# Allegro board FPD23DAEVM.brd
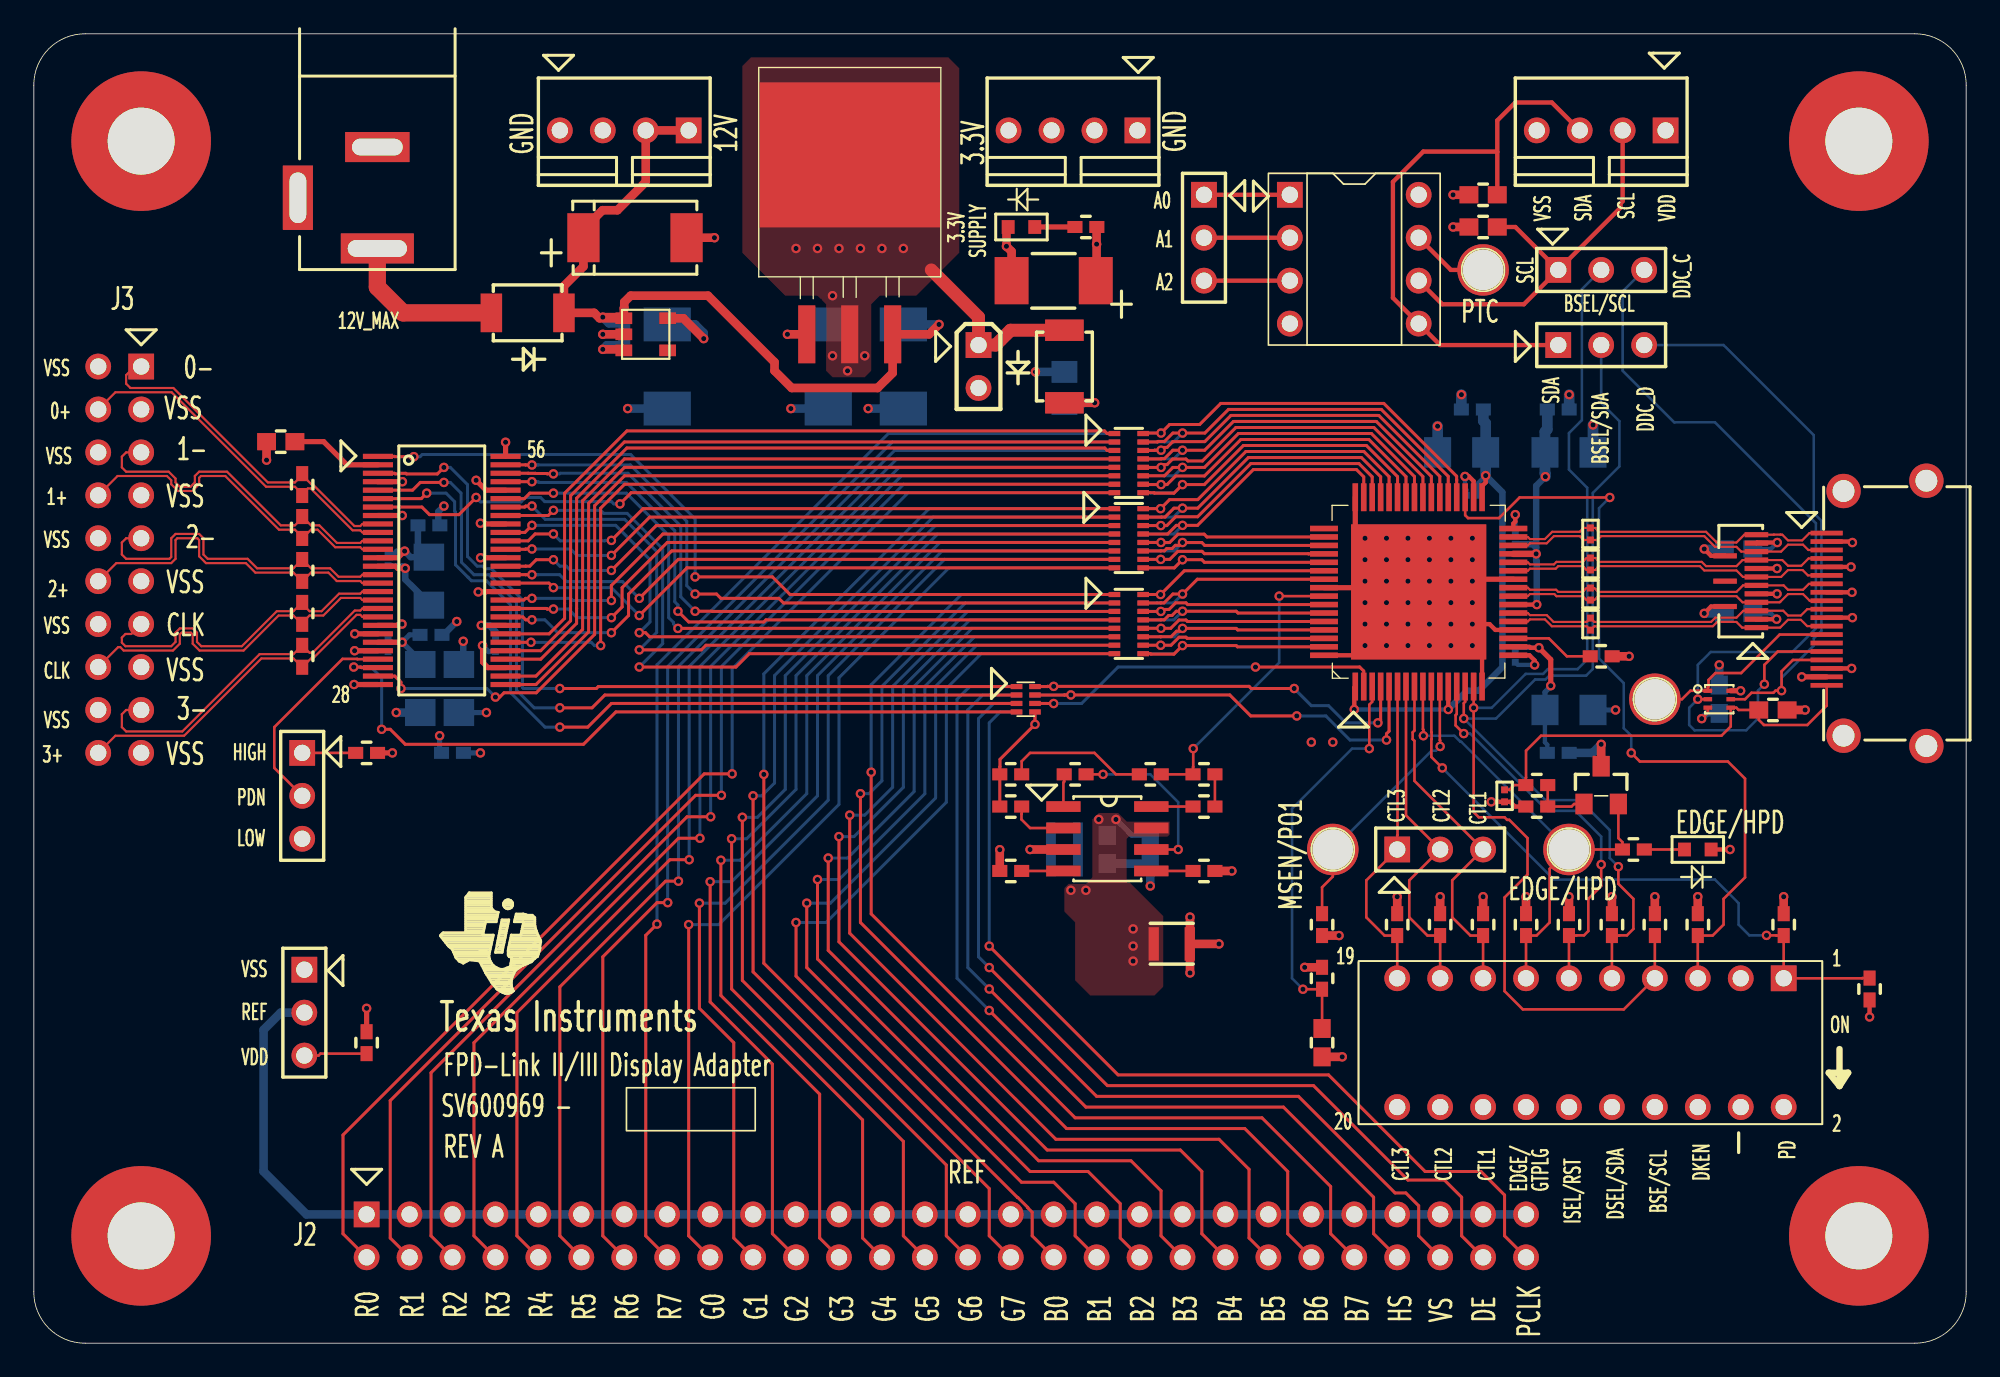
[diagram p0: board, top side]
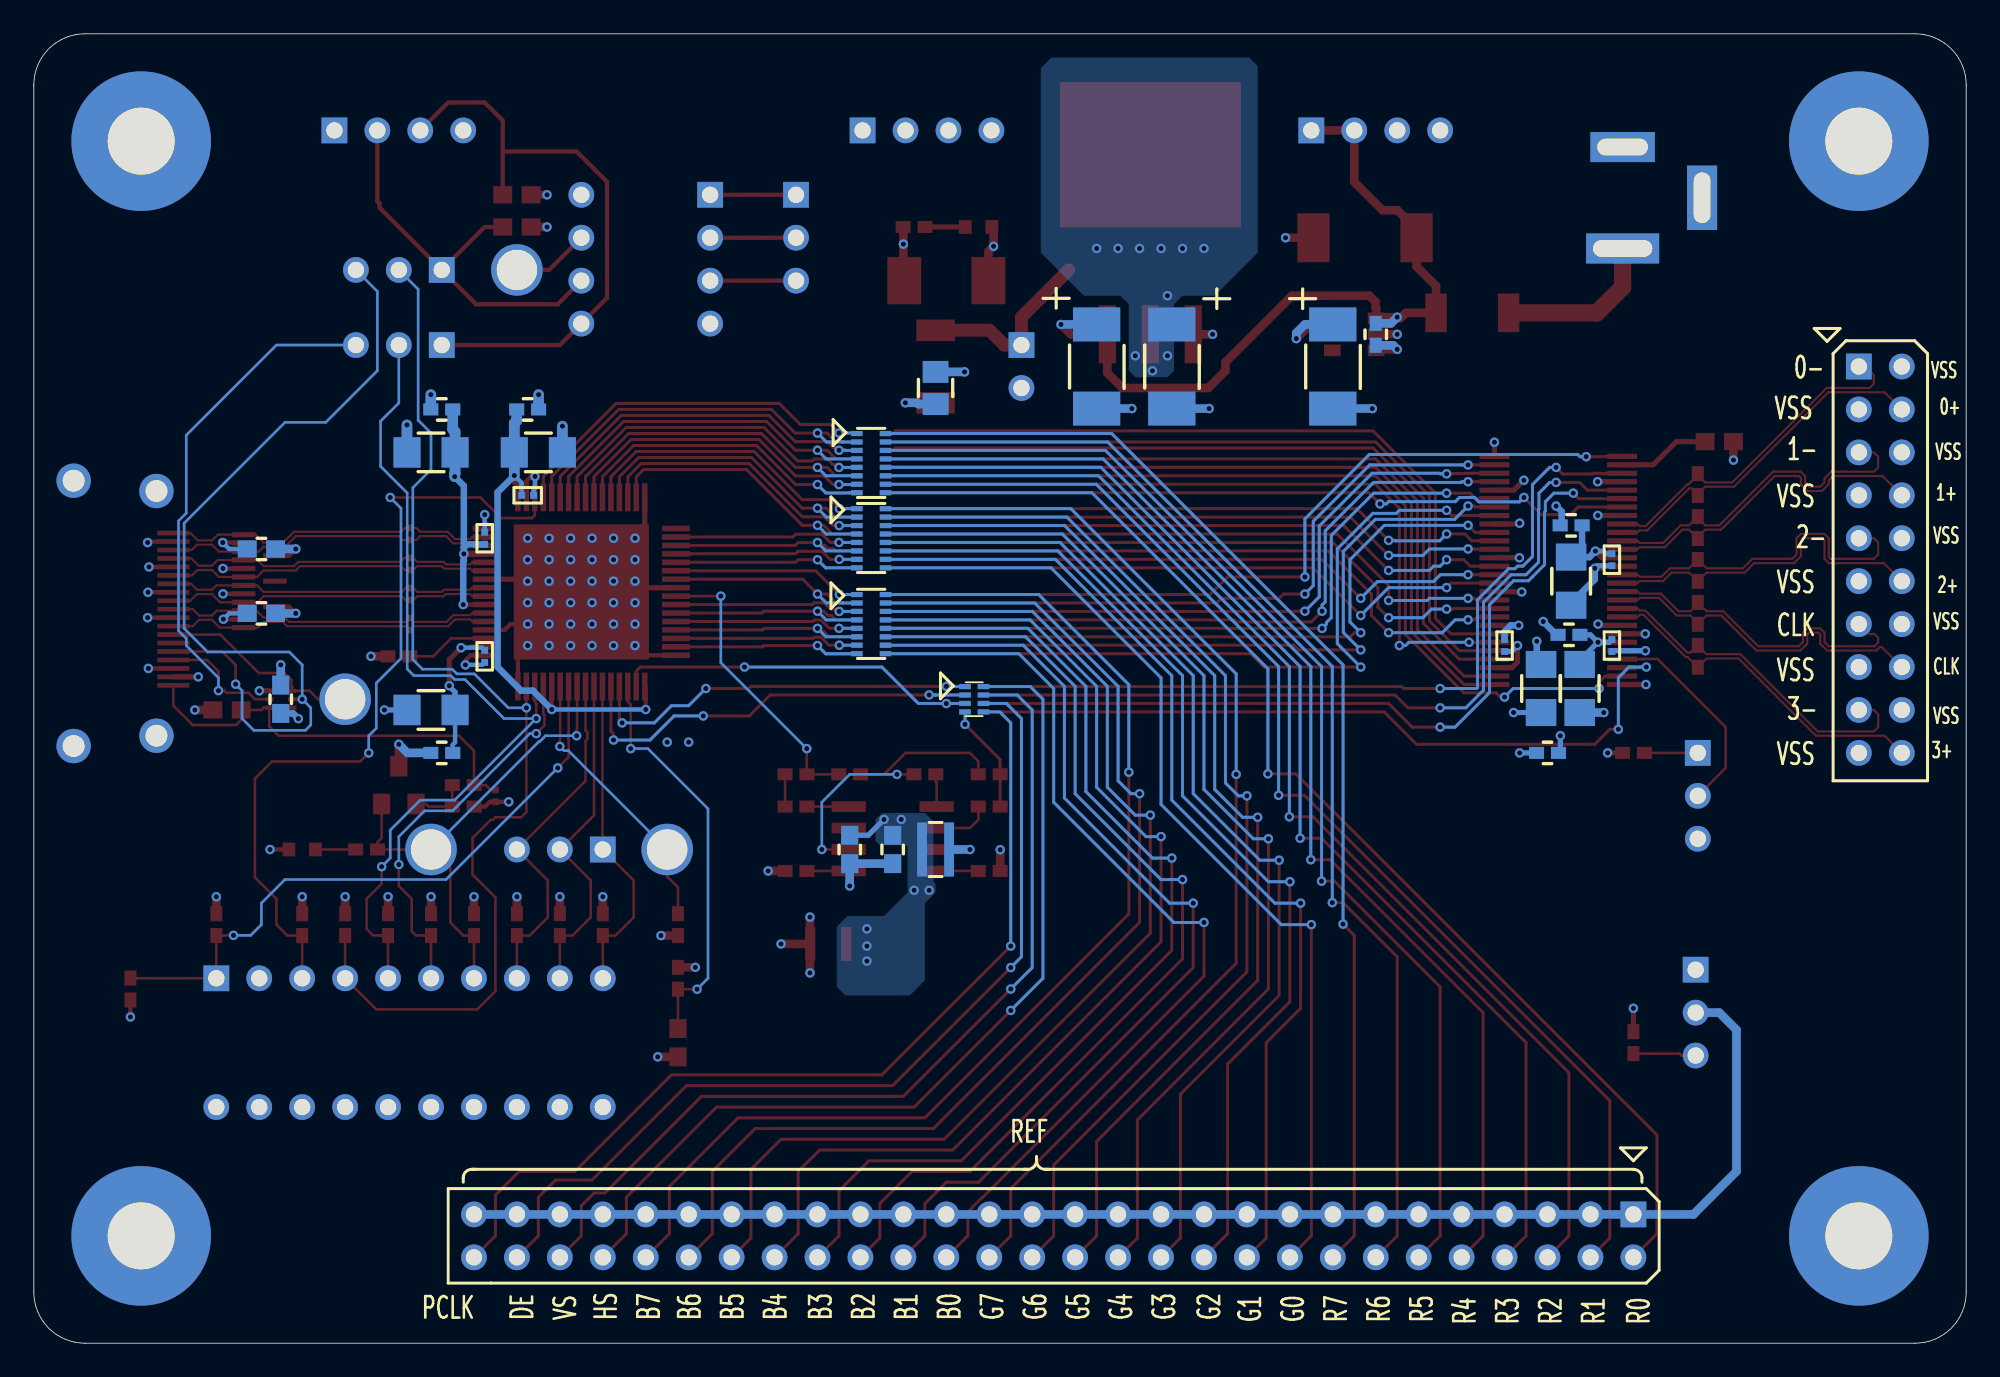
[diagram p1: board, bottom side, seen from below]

Outline 114.3 x 77.47 mm; copper layers: TOP, LYR_2, LYR_3, BOTTOM. Coordinates in mm from the lower left corner of the outline.
Outline path: 0,74.45 arc(0.89,76.59) 3.05,77.47 111.25,77.47 arc(113.41,76.59) 114.3,74.45 114.3,3.05 arc(113.42,0.89) 111.28,0 3.02,0 arc(0.88,0.89) 0,3.05 0,74.45

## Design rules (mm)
net group CLOCK: nets C+ C-
net group DATA0: nets 0+ 0-
net group DATA1: nets 1+ 1-
net group DATA2: nets 2+ 2-
net group RXCLKIN: nets RXCLKIN+ RXCLKIN-
net group RXIN0: nets RXIN0+ RXIN0-
net group RXIN1: nets RXIN1+ RXIN1-
net group RXIN2: nets RXIN2+ RXIN2-
net group RXIN3: nets RXIN3+ RXIN3-
nets with their own width: min track width 0.178; nets //G0 //G1 //R0 B0 B1 B2 B3 B4 B5 B6 B7 DE G0 G1 G2 G3 G4 G5 G6 G7 HS N15691374 N15691376 N15691378 N15691380 N15691382 N15691384 N15691386 N15693021 N15693494 N15693496 N15693498 N15693502 N15693504 N15693506 N15693508 N15694906 N15694908 N15694910 N15694912 N15695898 N15695900 N15695902 N15695904 N15695906 N15695908 N15695910 N15695912 N15696379 N15736550 N15737945 N15738621 N15739305 N15741654 N15742354 N15743062 N15744198 N15747608 N15748336 N15750252 N15751370 N15751746 N15752124 N15752504 N15752886 N15754502 N15759288 N15761170 N15764711 N15767513 N15768326 N15769147 N15769559 N15769973 PCLK R0 R1 R2 R3 R4 R5 R6 R7 VS

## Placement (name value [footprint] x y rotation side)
C1  22uF  [2917]  35.56 65.41 0 top
C2  10uF  [2312]  51.44 57.78 270 bottom
C3  10uF  [2312]  46.99 57.78 270 bottom
C4  0.1uF  [0805]  60.96 56.52 270 bottom
C5  10uF  [2312]  60.33 62.87 180 top
C6  22uF  [1206]  84.45 52.7 180 bottom
C7  0.1uF  [0201]  85.09 50.16 0 bottom
C8  0.1uF  [0201]  87.63 40.64 90 bottom
C9  0.1uF  [0201]  87.63 47.62 270 bottom
C10  22uF  [1206]  90.81 37.47 0 bottom
C11  0.1uF  [0603]  99.69 38.1 90 bottom
C12  22uF  [1206]  90.81 52.7 0 bottom
C13  0.1uF  [0603]  100.84 46.99 180 bottom
C14  0.1uF  [0603]  100.84 43.18 180 bottom
C15  0.01uF  [0603]  66.04 29.21 270 bottom
C16  0.1uF  [0603]  63.5 29.21 270 bottom
C17  10uF  [0612]  60.96 29.21 180 bottom
C18  1.0uF  [0402]  108.58 20.95 90 top
C19  0.1uF  [0201]  27.3 41.27 270 bottom
C20  0.1uF  [0201]  20.95 46.35 90 bottom
C21  0.1uF  [0201]  20.95 41.27 90 bottom
C22  1.0uF  [0402]  34.92 59.69 90 bottom
C23  10uH  [2312]  37.47 57.78 270 bottom
C24  22uF  [1206]  22.86 38.73 270 bottom
C25  22uF  [1206]  23.37 45.09 270 bottom
C26  22uF  [1206]  25.15 38.73 90 bottom
C27  0.1uF  [0201]  87 32.38 90 top
D1  LED  [0603_LED]  58.42 66.04 180 top
D2  LED  [0603_LED]  98.42 29.21 0 top
D3  DIODE SCHOTTKY  [SMA]  60.96 57.78 270 top
D4  DIODE SCHOTTKY  [SMA]  29.21 60.96 0 top
FB1  600ohm,250mA  [0402]  85.09 55.24 0 bottom
FB2  600ohm,250mA  [0402]  90.17 34.92 180 bottom
FB3  600ohm,250mA  [0402]  90.17 55.24 180 bottom
FB4  600ohm,250mA  [0402]  24.77 34.92 0 bottom
FB5  600ohm,250mA  [0402]  23.37 48.39 180 bottom
FB6  600ohm,250mA  [0402]  23.5 41.91 180 bottom
J1  12V  [HEADER_4P]  38.73 71.75 180 top
J2  Female HEADER 28x2  [HEADER_28X2_FEMALE]  19.68 7.62 270 bottom
J3  HEADER 10X2  [HEADER_10X2_FEMALE]  6.35 57.78 180 bottom
J4  HDMI Type A 732-2737-2-ND  [HDMICONN]  106.05 43.18 90 top
J5  3.3V  [HEADER_4P]  65.28 71.75 180 top
J6  CONN JACK PWR  [DC_PWR_JACK]  20.32 64.77 90 top
J7  HEADER 4  [HEADER_4P]  96.52 71.75 180 top
JP1  3-Pin Header  [HEADER_3P]  80.64 29.21 0 top
JP2  3-Pin Header  [HEADER_3P]  15.88 34.92 270 top
JP3  3-Pin Header  [HEADER_3P]  90.17 63.5 0 top
JP4  3-Pin Header  [HEADER_3P]  90.17 59.05 0 top
JP5  3-Pin Header  [HEADER_3P]  69.22 67.94 270 top
JP6  3-Pin Header  [HEADER_3P]  16 22.1 270 top
JP7  JUMPER  [HEADER_2P]  55.88 59.05 0 top
L1  2.2uH  [1007]  67.31 23.62 0 top
NOREF  -  [unnamed]  107.95 71.12 0 top
NOREF#2  -  [unnamed]  107.95 6.35 0 top
NOREF#3  -  [#2]  0 73.03 0 top
NOREF#4  -  [unnamed]  6.35 6.35 0 top
NOREF#5  -  [unnamed]  6.35 71.12 0 top
NOREF#6  -  [#2]  2.67 0.02 90 top
Q1  BSS123  [SOT_23]  92.71 33.02 0 top
R1  220  [0402]  62.23 66.04 0 top
R2  10k  [0402]  19.68 34.92 180 top
R3  4.7K  [0402]  88.9 31.75 180 top
R4  1K_NO_STUFF  [0402]  88.9 33.02 180 top
R5  510  [0402]  92.71 40.64 180 top
R6  220  [0402]  94.61 29.21 0 top
R7  0  [0402]  76.2 21.59 90 top
R8  ADJ-NO-STUFF  [0603]  76.2 17.78 90 top
R9  5.1K  [0402]  76.2 24.77 270 top
R10  10K  [0402]  80.64 24.77 90 top
R11  10K  [0402]  83.19 24.77 90 top
R12  10K  [0402]  85.72 24.77 90 top
R13  1K  [0402]  88.27 24.77 90 top
R14  10K  [0402]  90.81 24.77 90 top
R15  5.1K  [0402]  93.34 24.77 90 top
R16  5.1K  [0402]  95.89 24.77 90 top
R17  10K  [0402]  98.42 24.77 90 top
R18  10K  [0402]  103.5 24.77 90 top
R19  4.7K  [0603]  85.72 66.04 0 top
R20  0  [0402]  57.78 27.94 0 top
R21  0  [0402]  69.22 27.94 180 top
R22  22  [0402]  69.22 31.75 180 top
R23  22  [0402]  61.59 33.66 0 top
R24  0  [0402]  57.78 31.75 180 top
R25  4.7K  [0603]  85.72 67.94 0 top
R26  0-NO STUFF  [0603]  14.61 53.34 0 top
R27  100  [0402]  15.88 43.18 270 top
R28  100  [0402]  15.88 40.64 270 top
R29  100  [0402]  15.88 45.72 270 top
R30  100  [0402]  15.88 48.26 270 top
R31  100  [0402]  15.88 50.8 270 top
R32  0-NO-STUFF  [0402]  57.78 33.66 180 top
R33  0-NO-STUFF  [0402]  66.04 33.66 180 top
R34  0  [0402]  69.22 33.66 0 top
R35  NO STUFF  [0603]  102.87 37.47 180 top
R36  10K  [0402]  19.68 17.78 90 top
R37  NO STUFF  [0201]  92.08 47.88 270 top
R38  NO STUFF  [0201]  92.08 46.1 270 top
R39  NO STUFF  [0201]  92.08 44.32 270 top
R40  NO STUFF  [0201]  92.08 42.55 270 top
RN1  RESAR_IS_8/SM  [RN_1506]  64.77 52.07 180 bottom
RN2  RESAR_IS_8/SM  [RN_1506]  64.77 47.62 180 bottom
RN3  RESAR_IS_8/SM  [RN_1506]  64.77 42.55 180 bottom
RN4  RESAR_IS_4/SM  [RN_0804]  58.67 38.1 180 bottom
RN5  RESAR_IS_8/SM  [RN_1506]  64.77 52.07 0 top
RN6  RESAR_IS_8/SM  [RN_1506]  64.77 47.62 0 top
RN7  RESAR_IS_8/SM  [RN_1506]  64.77 42.55 0 top
RN8  RESAR_IS_4/SM  [RN_0804]  58.67 38.1 0 top
S1  SW  [DIP_SW_10POS]  103.5 21.59 270 top
TP1  TEST POINT  [TEST_POINT]  90.81 29.21 0 top
TP2  TEST POINT  [TEST_POINT]  95.89 38.1 0 top
TP3  TEST POINT  [TEST_POINT]  85.72 63.5 0 top
TP4  TEST POINT  [TEST_POINT]  76.83 29.21 0 top
U1  TFP410  [64L_TQFP]  81.92 44.45 90 top
U2  TPD4E001  [6_USON]  99.69 38.1 270 top
U3  DIP8 SOCKET(PCF8582C-2)  [DIP8]  74.3 67.94 0 top
U4  DS90CF386  [56_TSSOP]  24.13 45.72 270 top
U5  CY2302  [8_SOIC]  63.5 29.84 270 top
U6  REG1117-3.3/SOT  [TO_263_4]  48.26 59.69 270 top
U7  TPD8S009  [15_SON]  100.97 45.09 90 top
U8  TPS76950-Q1  [SOT_23_5]  36.2 59.69 0 top

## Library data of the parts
C1-C3 C5 C6 C10 C12 C23-C26 = CAPACITOR POL_1
C4 C7-C9 C11 C13 C14 C18-C22 C27 = C
C15 C16 = CAPACITOR NON-POL_0
C17 = CAPACITOR NON-POL_1
D1 D2 = LED
D3 D4 = DIODE SCHOTTKY
FB1-FB6 = INDUCTOR FERRITE
J1 J5 J7 = HEADER 4
J2 = HEADER 28x2
J3 = HEADER 10X2
J4 = CONN_HDMI_0: Tolerance: TOL; User Part Number: PART#
J6 = CONN JACK PWR
JP1-JP6 = JUMPER_12
JP7 = JUMPER_6
L1 = INDUCTOR
Q1 = BSS123_0
R1 = R_4
R2 = R_7
R3 R4 R6-R13 R15-R21 R35 R36 = R_6
R5 = R_14
R14 = R_1
R22 = R_8
R23 = R_9
R24 = R_10
R25 = R_0
R26 = R_5
R27-R30 R37-R40 = RESISTOR
R31 = RESISTOR_0
R32 = R_11
R33 = R_12
R34 = R_13
RN1-RN3 RN5-RN7 = RESAR_IS_8/SM
RN4 RN8 = RESAR_IS_4/SM
S1 = SW SMD-10_0
TP1-TP4 = TEST POINT
U1 = TFP410_0
U2 = TMS4C1070_8
U3 = DIP8 SOCKET
U4 = DS90CF384/SO_1
U5 = PKG_SOIC8_0
U6 = REG1117/SOT_2
U7 = TMS4C1070_7
U8 = TPS7133Q/HSOP_3

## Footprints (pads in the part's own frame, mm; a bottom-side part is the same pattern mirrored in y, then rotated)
6_USON
  rect 0.254x0.508 smd: 1(-0.5,-0.678) 2(0,-0.678) 3(0.5,-0.678) 4(0.5,0.678) 5(0,0.678) 6(-0.5,0.678)
8_SOIC
  rect 0.635x2.032 smd: 1(-1.905,-2.6) 2(-0.635,-2.6) 3(0.635,-2.6) 4(1.905,-2.6) 5(1.905,2.6) 6(0.635,2.6) 7(-0.635,2.6) 8(-1.905,2.6)
15_SON
  rect 0.305x1.397 smd: 1(-2.749,-0.927) 2(-2.249,-0.927) 3(-1.75,-0.927) 4(-1.25,-0.927) 5(-0.75,-0.927) 6(-0.25,-0.927) 7(0.25,-0.927) 8(0.75,-0.927) 9(1.25,-0.927) 10(1.75,-0.927) 11(2.249,-0.927) 12(2.749,-0.927) 13(1.5,0.927) 14(0,0.927) 15(-1.5,0.927)
56_TSSOP
  rect 0.305x1.778 smd: 1(-6.75,-3.775) 2(-6.25,-3.775) 3(-5.75,-3.775) 4(-5.25,-3.775) 5(-4.75,-3.775) 6(-4.25,-3.775) 7(-3.75,-3.775) 8(-3.25,-3.775) 9(-2.75,-3.775) 10(-2.25,-3.775) 11(-1.75,-3.775) 12(-1.25,-3.775) 13(-0.75,-3.775) 14(-0.25,-3.775) 15(0.25,-3.775) 16(0.75,-3.775) 17(1.25,-3.775) 18(1.75,-3.775) 19(2.25,-3.775) 20(2.75,-3.775) 21(3.25,-3.775) 22(3.75,-3.775) 23(4.25,-3.775) 24(4.75,-3.775) 25(5.25,-3.775) 26(5.75,-3.775) 27(6.25,-3.775) 28(6.75,-3.775) 29(6.75,3.775) 30(6.25,3.775) 31(5.75,3.775) 32(5.25,3.775) 33(4.75,3.775) 34(4.25,3.775) 35(3.75,3.775) 36(3.25,3.775) 37(2.75,3.775) 38(2.25,3.775) 39(1.75,3.775) 40(1.25,3.775) 41(0.75,3.775) 42(0.25,3.775) 43(-0.25,3.775) 44(-0.75,3.775) 45(-1.25,3.775) 46(-1.75,3.775) 47(-2.25,3.775) 48(-2.75,3.775) 49(-3.25,3.775) 50(-3.75,3.775) 51(-4.25,3.775) 52(-4.75,3.775) 53(-5.25,3.775) 54(-5.75,3.775) 55(-6.25,3.775) 56(-6.75,3.775)
64L_TQFP
  rect 1.651x0.33 smd: 1(-5.6,3.75) 2(-5.6,3.25) 3(-5.6,2.75) 4(-5.6,2.25) 5(-5.6,1.75) 6(-5.6,1.25) 7(-5.6,0.75) 8(-5.6,0.25) 9(-5.6,-0.25) 10(-5.6,-0.75) 11(-5.6,-1.25) 12(-5.6,-1.75) 13(-5.6,-2.25) 14(-5.6,-2.75) 15(-5.6,-3.25) 16(-5.6,-3.75) 33(5.6,-3.75) 34(5.6,-3.25) 35(5.6,-2.75) 36(5.6,-2.25) 37(5.6,-1.75) 38(5.6,-1.25) 39(5.6,-0.75) 40(5.6,-0.25) 41(5.6,0.25) 42(5.6,0.75) 43(5.6,1.25) 44(5.6,1.75) 45(5.6,2.25) 46(5.6,2.75) 47(5.6,3.25) 48(5.6,3.75)
  rect 0.33x1.651 smd: 17(-3.75,-5.6) 18(-3.25,-5.6) 19(-2.75,-5.6) 20(-2.25,-5.6) 21(-1.75,-5.6) 22(-1.25,-5.6) 23(-0.75,-5.6) 24(-0.25,-5.6) 25(0.25,-5.6) 26(0.75,-5.6) 27(1.25,-5.6) 28(1.75,-5.6) 29(2.25,-5.6) 30(2.75,-5.6) 31(3.25,-5.6) 32(3.75,-5.6) 49(3.75,5.6) 50(3.25,5.6) 51(2.75,5.6) 52(2.25,5.6) 53(1.75,5.6) 54(1.25,5.6) 55(0.75,5.6) 56(0.25,5.6) 57(-0.25,5.6) 58(-0.75,5.6) 59(-1.25,5.6) 60(-1.75,5.6) 61(-2.25,5.6) 62(-2.75,5.6) 63(-3.25,5.6) 64(-3.75,5.6)
  rect 8.001x8.001 smd: 65(0,0)
0201
  rect 0.406x0.406 smd: 1(-0.356,0) 2(0.356,0)
0402
  rect 0.889x0.711 smd: 1(-0.648,0) 2(0.648,0)
0603
  rect 1.118x1.016 smd: 1(-0.838,0) 2(0.838,0)
0603_LED
  rect 0.762x0.813 smd: 1(-0.787,0) 2(0.787,0)
0612
  rect 0.584x3.2 smd: 1(-0.8,0) 2(0.8,0)
0805
  rect 1.295x1.524 smd: 1(-0.953,0) 2(0.953,0)
1007
  rect 0.61x1.981 smd: 1(-1.067,0) 2(1.067,0)
1206
  rect 1.6x1.803 smd: 1(-1.422,0) 2(1.422,0)
2312
  rect 2.007x2.794 smd: 1(-2.489,0) 2(2.489,0)
2917
  rect 1.905x2.896 smd: 1(-3.05,0) 2(3.05,0)
DC_PWR_JACK
  rect 1.778x4.318 hole 0.991x3.505: 1(0,0)
  rect 1.778x3.81 hole 0.991x2.997: 2(6,0)
  rect 3.81x1.778 hole 2.997x0.991: 3(3,4.7)
DIP8
  rect 1.524x1.524 hole 0.965: 1(0,0)
  round 1.524 hole 0.965: 2(0,-2.54) 3(0,-5.08) 4(0,-7.62) 5(7.62,-7.62) 6(7.62,-5.08) 7(7.62,-2.54) 8(7.62,0)
DIP_SW_10POS
  rect 1.524x1.524 hole 0.965: 1(0,0)
  round 1.524 hole 0.965: 2(7.62,0) 3(0,-2.54) 4(7.62,-2.54) 5(0,-5.08) 6(7.62,-5.08) 7(0,-7.62) 8(7.62,-7.62) 9(0,-10.16) 10(7.62,-10.16) 11(0,-12.7) 12(7.62,-12.7) 13(0,-15.24) 14(7.62,-15.24) 15(0,-17.78) 16(7.62,-17.78) 17(0,-20.32) 18(7.62,-20.32) 19(0,-22.86) 20(7.62,-22.86)
HDMICONN
  round 2.032 hole 1.295: (-7.849,-5.9) (-7.239,-1.001) (7.239,-1.001) (7.849,-5.9)
  rect 0.279x1.905 smd: 1(4.75,0) 2(4.249,0) 3(3.749,0) 4(3.249,0) 5(2.748,0) 6(2.248,0) 7(1.748,0) 8(1.247,0) 9(0.747,0) 10(0.246,0) 11(-0.254,0) 12(-0.754,0) 13(-1.255,0) 14(-1.755,0) 15(-2.256,0) 16(-2.756,0) 17(-3.256,0) 18(-3.757,0) 19(-4.257,0)
HEADER_2P
  rect 1.524x1.524 hole 0.965: 1(0,0)
  round 1.524 hole 0.965: 2(0,-2.54)
HEADER_3P
  rect 1.524x1.524 hole 0.965: 1(0,0)
  round 1.524 hole 0.965: 2(2.54,0) 3(5.08,0)
HEADER_4P
  rect 1.524x1.524 hole 0.965: 1(0,0)
  round 1.524 hole 0.965: 2(2.54,0) 3(5.08,0) 4(7.62,0)
HEADER_10X2_FEMALE
  rect 1.524x1.524 hole 0.965: 1(0,0)
  round 1.524 hole 0.965: 2(2.54,0) 3(0,-2.54) 4(2.54,-2.54) 5(0,-5.08) 6(2.54,-5.08) 7(0,-7.62) 8(2.54,-7.62) 9(0,-10.16) 10(2.54,-10.16) 11(0,-12.7) 12(2.54,-12.7) 13(0,-15.24) 14(2.54,-15.24) 15(0,-17.78) 16(2.54,-17.78) 17(0,-20.32) 18(2.54,-20.32) 19(0,-22.86) 20(2.54,-22.86)
HEADER_28X2_FEMALE
  rect 1.524x1.524 hole 0.965: 1(0,0)
  round 1.524 hole 0.965: 2(2.54,0) 3(0,-2.54) 4(2.54,-2.54) 5(0,-5.08) 6(2.54,-5.08) 7(0,-7.62) 8(2.54,-7.62) 9(0,-10.16) 10(2.54,-10.16) 11(0,-12.7) 12(2.54,-12.7) 13(0,-15.24) 14(2.54,-15.24) 15(0,-17.78) 16(2.54,-17.78) 17(0,-20.32) 18(2.54,-20.32) 19(0,-22.86) 20(2.54,-22.86) 21(0,-25.4) 22(2.54,-25.4) 23(0,-27.94) 24(2.54,-27.94) 25(0,-30.48) 26(2.54,-30.48) 27(0,-33.02) 28(2.54,-33.02) 29(0,-35.56) 30(2.54,-35.56) 31(0,-38.1) 32(2.54,-38.1) 33(0,-40.64) 34(2.54,-40.64) 35(0,-43.18) 36(2.54,-43.18) 37(0,-45.72) 38(2.54,-45.72) 39(0,-48.26) 40(2.54,-48.26) 41(0,-50.8) 42(2.54,-50.8) 43(0,-53.34) 44(2.54,-53.34) 45(0,-55.88) 46(2.54,-55.88) 47(0,-58.42) 48(2.54,-58.42) 49(0,-60.96) 50(2.54,-60.96) 51(0,-63.5) 52(2.54,-63.5) 53(0,-66.04) 54(2.54,-66.04) 55(0,-68.58) 56(2.54,-68.58)
RN_0804
  rect 0.686x0.305 smd: 1(-0.546,0.75) 2(-0.546,0.25) 3(-0.546,-0.25) 4(-0.546,-0.75) 5(0.546,-0.75) 6(0.546,-0.25) 7(0.546,0.25) 8(0.546,0.75)
RN_1506
  rect 0.686x0.305 smd: 1(-0.851,1.75) 2(-0.851,1.25) 3(-0.851,0.75) 4(-0.851,0.25) 5(-0.851,-0.25) 6(-0.851,-0.75) 7(-0.851,-1.25) 8(-0.851,-1.75) 9(0.851,-1.75) 10(0.851,-1.25) 11(0.851,-0.75) 12(0.851,-0.25) 13(0.851,0.25) 14(0.851,0.75) 15(0.851,1.25) 16(0.851,1.75)
SMA
  rect 1.27x2.286 smd: 1(-2.146,0) 2(2.146,0)
SOT_23
  rect 1.016x1.219 smd: 1(-1.016,-1.118) 2(1.016,-1.118) 3(0,1.118)
SOT_23_5
  rect 0.991x0.686 smd: 1(-1.295,0.95) 2(-1.295,0) 3(-1.295,-0.95) 4(1.295,-0.95) 5(1.295,0.95)
TEST_POINT
  round 3.048 hole 2.388: 1(0,0)
TO_263_4
  rect 3.429x1.016 smd: 1(0,-2.54) 2(0,0) 3(0,2.54)
  rect 8.585x10.693 smd: 4(-10.617,0)
unnamed
  round 8.255 hole 3.962: (0,0)

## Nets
3.3V: C4.2 C5.1 C11.2 C13.2 C14.2 D3.2(CATHODE) FB1.1 FB2.1 FB3.1 FB4.1 FB5.1 FB6.1 J5.3 J5.4 J7.1 JP7.2 L1.2 Q1.3(DRAIN) R1.2 R5.1 R7.2 R9.2 R10.2 R11.2 R12.2 R13.2 R14.2 R15.2 R16.2 R17.2 R18.2 R36.2 U2.6(VCC) U7.13(VCC#13) U7.15(VCC#15)
+5V: C23.1 J4.18(+5V) R19.1 R25.1 R35.1 U3.8 U8.5(OUT)
DVDD: C6.1 C7.2 FB1.2 U1.1(DVDD#1) U1.12(DVDD#12) U1.33(DVDD#33)
PVDD: C8.2 C10.1 FB2.2 U1.18(PVDD)
VCC: C19.2 C26.1 FB4.2 R2.1 U4.31(VCC#31) U4.40(VCC#40) U4.48(VCC#48) U4.56(VCC#56)
VDD12VMAX: C1.1 C2.1 C22.2 D4.2(CATHODE) J1.1 J1.2 U6.3(VIN) U8.1(IN)
VSS: C1.2 C2.2 C3.2 C4.1 C5.2 C6.2 C7.1 C8.1 C9.1 C10.2 C11.1 C12.2 C13.1 C14.1 C15.2 C16.2 C17.2 C18.1 C19.1 C20.1 C21.1 C22.1 C23.2 C24.2 C25.2 C26.2 C27.1 D1.2(CATHODE) D2.2(CATHODE) J1.3 J1.4 J3.2 J3.3 J3.6 J3.7 J3.10 J3.11 J3.14 J3.15 J3.18 J3.19 J4.2(DAT2_S) J4.5(DAT1_S) J4.8(DAT0_S) J4.11(CLK_S) J4.17(DDC/CEC GND) J5.1 J5.2 J6.2 J6.3 J7.4 JP2.3 JP6.1 R3.2 R8.1 R20.1 R21.1 R26.1 S1.2(B1) S1.4(B2) S1.6(B3) S1.8(B4) S1.10(B5) S1.12(B6) S1.14(B7) S1.16(B8) S1.18(B9) S1.20(B10) U1.16(DGND#16) U1.17(PGND) U1.20(TGND#20) U1.26(TGND#26) U1.32(TGND#32) U1.34(RESERVED) U1.48(DGND#48) U1.56(IDCK-) U1.64(DGND#64) U1.65(PAD) U2.3(GND) U3.4 U4.4(GND#4) U4.8(LVDSGND#8) U4.14(LVDSGND#14) U4.21(LVDSGND#21) U4.22(PLLGND#22) U4.24(PLLGND#24) U4.28(GND#28) U4.36(GND#36) U4.44(GND#44) U4.52(GND#52) U5.3(GND) U6.1(GND) U7.2(GND#2) U7.5(GND#5) U7.8(GND#8) U7.11(GND#11) U8.2(GND) U8.3(E\N\)
0+: J4.7(DAT0+) R39.1 U1.25(TX0+) U7.6(D1-)
0-: J4.9(DAT0-) R39.2 U1.24(TX0-) U7.4(D1+)
1+: J4.4(DAT1+) R38.1 U1.28(TX1+) U7.9(D2-)
1-: J4.6(DAT1-) R38.2 U1.27(TX1-) U7.7(D2+)
2+: J4.1(DAT2+) R37.1 U1.31(TX2+) U7.12(D3-)
2-: J4.3(DAT2-) R37.2 U1.30(TX2-) U7.10(D3+)
//G0: RN6.8 U4.41(RXOUT10)
//G1: RN6.7 U4.42(RXOUT11)
//R0: RN5.8 U4.7(RXOUT27)
B0: RN3.8 RN7.9 U1.63(DATA0)
B1: RN3.7 RN7.10 U1.62(DATA1)
B2: RN3.6 RN7.11 U1.61(DATA2)
B3: RN3.5 RN7.12 U1.60(DATA3)
B4: RN3.4 RN7.13 U1.59(DATA4)
B5: RN3.3 RN7.14 U1.58(DATA5)
B6: RN3.2 RN7.15 U1.55(DATA6)
B7: RN3.1 RN7.16 U1.54(DATA7)
BSEL/SCL: JP3.2 R16.1 S1.7(A4) U1.15(BSEL)
C+: J4.10(CLK+) R40.1 U1.22(TXC+) U7.3(D0-)
C-: J4.12(CLK-) R40.2 U1.21(TXC-) U7.1(D0+)
CEC: J4.13(CEC) TP2.1 U2.1(IO1)
CTL1: JP1.3 R12.1 S1.15(A8) U1.8(CTL1)
CTL2: JP1.2 R11.1 S1.17(A9) U1.7(CTL2)
CTL3: JP1.1 R10.1 S1.19(A10) U1.6(CTL3)
D_PCLK: R33.1 R34.1 U1.57(IDCK+)
DDC_C: J4.15(SCL) JP3.3 U2.2(IO2)
DDC_D: J4.16(SDA) JP4.3 U2.5(IO4)
DE: RN4.3 RN8.6 U1.2(DE)
DKEN: R17.1 S1.5(A3) U1.35(DKEN)
DSEL/SDA: JP4.2 R15.1 S1.9(A5) U1.14(DSEL)
EDGE/HTPLG: Q1.2(SOURCE) R6.1 R13.1 S1.13(A7) TP1.1 U1.9(EDGE)
FBIN: R23.1 U5.1(FBIN)
G0: RN2.8 RN6.9 U1.53(DATA8)
G1: RN2.7 RN6.10 U1.52(DATA9)
G2: RN2.6 RN6.11 U1.51(DATA10)
G3: RN2.5 RN6.12 U1.50(DATA11)
G4: RN2.4 RN6.13 U1.47(DATA12)
G5: RN2.3 RN6.14 U1.46(DATA13)
G6: RN2.2 RN6.15 U1.45(DATA14)
G7: RN2.1 RN6.16 U1.44(DATA15)
HOT_PLUG: C27.2 J4.19(HPLG) R4.2 R35.2 U2.4(IO3)
HS: RN4.1 RN8.8 U1.4(HSYNC)
ISEL/RST: R14.1 S1.11(A6) U1.13(ISEL)
LVDSVCC: C20.2 C25.1 FB5.2 U4.13(LVDSVCC)
MSEN/PO1: R9.1 TP4.1 U1.11(MSEN)
PCLK: R24.2 R32.2 RN4.4 RN8.5
PCLK_IN: R24.1 U5.2(IN)
PCLK_OUT: R22.1 R34.2
PD: C18.2 R18.1 S1.1(A1) U1.10(PD)
PDN: JP2.2 U4.25(P\D\N\)
PLLVCC: C21.2 C24.1 FB6.2 U4.23(PLLVCC)
R0: RN1.8 RN5.9 U1.43(DATA16)
R1: RN1.7 RN5.10 U1.42(DATA17)
R2: RN1.6 RN5.11 U1.41(DATA18)
R3: RN1.5 RN5.12 U1.40(DATA19)
R4: RN1.4 RN5.13 U1.39(DATA20)
R5: RN1.3 RN5.14 U1.38(DATA21)
R6: RN1.2 RN5.15 U1.37(DATA22)
R7: RN1.1 RN5.16 U1.36(DATA23)
RXCLKIN+: J3.16 R27.2 U4.18(RXCLKIN+)
RXCLKIN-: J3.13 R27.1 U4.17(RXCLKIN-)
RXIN0+: J3.4 R31.2 U4.10(RXIN0+)
RXIN0-: J3.1 R31.1 U4.9(RXIN0-)
RXIN1+: J3.8 R30.2 U4.12(RXIN1+)
RXIN1-: J3.5 R30.1 U4.11(RXIN1-)
RXIN2+: J3.12 R29.2 U4.16(RXIN2+)
RXIN2-: J3.9 R29.1 U4.15(RXIN2-)
RXIN3+: J3.20 R28.2 U4.20(RXIN3+)
RXIN3-: J3.17 R28.1 U4.19(RXIN3-)
SCL: J7.2 JP3.1 R19.2 U3.6
SDA: J7.3 JP4.1 R25.2 U3.5
TVDD: C9.2 C12.1 FB3.2 U1.23(TVDD#23) U1.29(TVDD#29)
VREF: R7.1 R8.2 U1.3(VREF)
VS: RN4.2 RN8.7 U1.5(VSYNC)
N14860968: J2.1 J2.3 J2.5 J2.7 J2.9 J2.11 J2.13 J2.15 J2.17 J2.19 J2.21 J2.23 J2.25 J2.27 J2.29 J2.31 J2.33 J2.35 J2.37 J2.39 J2.41 J2.43 J2.45 J2.47 J2.49 J2.51 J2.53 J2.55 JP6.2
N14861406: R5.2 U1.19(TFADJ)
N14862082: C15.1 C16.1 C17.1 L1.1 U5.7(VDD)
N15107145: JP2.1 R2.2
N15438976: D4.1(ANODE) J6.1
N15439034: C3.1 D3.1(ANODE) JP7.1 U6.2(VOUT) U6.4(TAB)
N15440280: JP5.1 U3.1
N15440284: JP5.2 U3.2
N15440292: JP5.3 U3.3
N15476881: D1.1(ANODE) R1.1
N15551732: Q1.1(GATE) R3.1 R4.1
N15559932: D2.1(ANODE) R6.2
N15593216: TP3.1 U3.7
N15691374: J2.14 RN1.15
N15691376: J2.12 RN1.14
N15691378: J2.10 RN1.13
N15691380: J2.4 RN1.10
N15691382: J2.8 RN1.12
N15691384: J2.2 RN1.9
N15691386: J2.6 RN1.11
N15693021: J2.16 RN1.16
N15693494: J2.24 RN2.12
N15693496: J2.22 RN2.11
N15693498: J2.20 RN2.10
N15693502: J2.18 RN2.9
N15693504: J2.30 RN2.15
N15693506: J2.28 RN2.14
N15693508: J2.26 RN2.13
N15694906: J2.50 RN4.8
N15694908: J2.52 RN4.7
N15694910: J2.54 RN4.6
N15694912: J2.56 RN4.5
N15695898: J2.42 RN3.13
N15695900: J2.44 RN3.14
N15695902: J2.40 RN3.12
N15695904: J2.46 RN3.15
N15695906: J2.48 RN3.16
N15695908: J2.38 RN3.11
N15695910: J2.36 RN3.10
N15695912: J2.34 RN3.9
N15696379: J2.32 RN2.16
N15736550: RN5.6 U4.27(RXOUT0)
N15737945: RN5.5 U4.29(RXOUT1)
N15738621: RN5.4 U4.30(RXOUT2)
N15739305: RN5.3 U4.32(RXOUT3)
N15741654: RN5.2 U4.33(RXOUT4)
N15742354: RN5.7 U4.34(RXOUT5)
N15743062: RN5.1 U4.35(RXOUT6)
N15744198: RN8.4 U4.26(RXCLKOUT)
N15747608: RN8.1 U4.3(RXOUT24)
N15748336: RN8.2 U4.5(RXOUT25)
N15750252: RN8.3 U4.6(RXOUT26)
N15750996: R26.2 U4.2(RXOUT23)
N15751370: RN7.1 U4.1(RXOUT22)
N15751746: RN7.2 U4.55(RXOUT21)
N15752124: RN7.3 U4.54(RXOUT20)
N15752504: RN7.4 U4.53(RXOUT19)
N15752886: RN7.5 U4.51(RXOUT18)
N15754502: RN7.7 U4.50(RXOUT17)
N15759288: RN7.8 U4.49(RXOUT16)
N15761170: RN7.6 U4.47(RXOUT15)
N15764711: RN6.1 U4.46(RXOUT14)
N15767513: RN6.2 U4.45(RXOUT13)
N15768326: RN6.3 U4.43(RXOUT12)
N15769147: RN6.6 U4.37(RXOUT7)
N15769559: RN6.5 U4.38(RXOUT8)
N15769973: RN6.4 U4.39(RXOUT9)
N15799422: R23.2 U5.6(OUT1)
N15814147: R32.1 R33.2
N15821065: R22.2 U5.8(OUT2)
N15926102: JP6.3 R36.1
N148619201: R21.2 U5.5(FS1)
N148620200: R20.2 U5.4(FS0)

Pads without a net: J4 14; S1 3; U1 49; U7 14; U8 4

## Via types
v1: diameter 0.559, hole 0.305, TOP to BOTTOM, 280 vias

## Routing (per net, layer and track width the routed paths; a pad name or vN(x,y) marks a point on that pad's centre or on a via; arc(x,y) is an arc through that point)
3.3V: length 61.3
  TOP w0.254: U7.13 99.21,46.58 v1(98.81,46.99) ; U7.15 99.21,43.59 v1(98.81,43.18)
  TOP w0.305: U2.6 v1(100.96,38.6) ; v1(19.68,19.81) R36.2
  TOP w0.508: R14.2 v1(90.81,26.42) ; v1(68.39,21.91) 68.39,23.61 L1.2 68.39,23.62 ; 68.39,23.62 v1(70.1,23.62) ; 68.39,23.62 v1(68.39,25.21) ; R13.2 v1(88.27,26.42) ; Q1.3 v1(92.71,35.43) ; R18.2 v1(103.5,26.42) ; R15.2 v1(93.34,26.42) ; R9.2 v1(77.2,24.12) ; R11.2 v1(83.19,26.42) ; D3.2 v1(62.75,55.64) ; R16.2 v1(95.89,26.42) ; R1.2 62.87,66.03 v1(62.87,65.02) 62.87,62.92 C5.1 ; R5.1 v1(94.36,40.64) ; R10.2 v1(80.64,26.42) ; R12.2 v1(85.72,26.42) ; R7.2 v1(75.17,22.24) ; R17.2 v1(98.42,26.42)
  LYR_3 w0.66: 56.76,70.86 J5.4 ; J5.4 58.55,70.86 ; J5.4 56.76,72.65 ; J5.4 58.55,72.65 ; J5.3 61.09,70.86 ; J5.3 59.3,72.65 ; J5.3 61.09,72.65 ; J5.3 59.3,70.86 ; 95.62,72.65 J7.1 ; J7.1 95.62,70.86 ; J7.1 97.42,72.65 ; J7.1 97.42,70.86 ; 54.98,57.41 JP7.2 ; JP7.2 56.78,55.62 ; JP7.2 54.98,55.62 ; JP7.2 56.78,57.41
  BOTTOM w0.305: FB4.1 24,35.04 v1(24,35.94)
  BOTTOM w0.381: FB6.1 24.23,41.91 v1(25.02,42.7) ; FB5.1 23.92,48.48 23.92,49.2 v1(24.26,49.53)
  BOTTOM w0.508: C13.2 v1(98.81,46.99) ; C14.2 v1(98.81,43.18) ; C4.2 61.98,55.56 62.05,55.64 v1(62.75,55.64) ; v1(92.71,35.43) 92.2,34.92 FB2.1 ; C11.2 v1(99.69,40.13)
  BOTTOM w0.635: FB3.1 v1(90.82,56.12) ; FB1.1 v1(84.44,56.12)
+5V: length 14.8
  TOP w0.305: J4.18 v1(104.57,39.42)
  TOP w0.508: v1(39.62,59.44) 38.42,60.64 U8.5 ; R35.1 v1(104.78,37.47) ; R19.1 v1(83.95,66.04) ; R25.1 v1(83.95,67.94)
  LYR_3 w0.66: 81.02,67.05 U3.8 ; U3.8 81.02,68.84 ; U3.8 82.81,68.84 ; U3.8 82.81,67.05
  BOTTOM w0.508: C23.1 39.12,60.27 39.62,59.77 v1(39.62,59.44)
DVDD: length 31
  TOP w0.254: U1.33 85.67,50.71 85.88,50.93 v1(85.88,51.33) ; v1(78.11,37.49) 78.11,38.79 U1.1 ; U1.12 v1(83.67,37.49)
  BOTTOM w0.254: v1(78.11,37.49) v1(83.67,37.49) ; v1(85.88,51.33) 85.45,50.9 C7.2
  BOTTOM w0.381: v1(85.88,51.33) 86.87,50.34 86.87,40.01 85.47,38.61 84.78,38.61 v1(83.67,37.49)
  BOTTOM w0.635: v1(85.88,51.33) C6.1 85.88,54.43 85.74,54.57 FB1.2
PVDD: length 9.7
  TOP w0.254: U1.18 88.47,41.2 88.52,41.15 v1(89.03,41.15)
  TOP w0.305: v1(89.73,38.9) 89.73,40.45 v1(89.03,41.15)
  BOTTOM w0.254: FB2.2 89.52,35.41 89.38,35.55 C10.1 ; v1(89.03,41.15) 87.78,41.15 C8.2
  BOTTOM w0.305: C10.1 89.38,38.52 89.73,38.86 v1(89.73,38.9)
VCC: length 11.3
  TOP w0.305: v1(26.29,44.45) 26.72,44.45 26.74,44.47 U4.40 ; U4.31 26.86,39.97 26.54,40.29 v1(26.54,41.27) ; R2.1 v1(21.21,34.92) ; U4.48 26.46,48.47 v1(26.42,48.51) ; U4.56 v1(27.9,53.3)
  BOTTOM w0.152: 26.61,41.21 26.61,41.18 26.87,40.92 26.9,40.92
  BOTTOM w0.305: C19.2 26.9,40.92 v1(26.54,41.27) ; C26.1 v1(26.77,37.31) ; FB4.2 v1(26.42,34.92)
VDD12VMAX: length 49.5
  TOP w0.508: J1.1 J1.2 36.2,68.71 34.52,67.03 33.64,67.03 32.51,65.9 C1.1 32.51,63.7 31.36,62.55 D4.2 33.15,60.96 33.47,60.64 U8.1 ; U8.1 34.9,61.24 34.92,61.26 34.92,61.59 35.31,61.98 39.88,61.98 43.81,58.04 43.81,57.53 44.83,56.52 49.91,56.52 50.8,57.4 U6.3 52.96,59.69 v1(53.54,60.27) ; U8.1 34.83,60.71 v1(33.66,60.71)
  BOTTOM w0.508: C22.2 34.02,60.34 v1(33.66,60.71) ; C2.1 v1(53.54,60.27)
VSS: length 269
  TOP w0.152: U2.3 99.02,37.29 98.81,37.08 98.81,36.95 v1(98.65,36.95)
  TOP w0.254: U1.16 85.67,40.7 v1(85.09,41.27) ; C18.1 v1(108.58,19.3) ; J4.5 v1(107.49,45.93) ; D2.2 v1(100.33,29.21) ; U1.64 78.16,40.7 v1(78.74,41.27) ; U7.5 v1(103.11,44.34) ; J4.8 v1(107.55,44.43) ; U1.20 86.45,42.2 86.11,42.55 v1(85.09,42.55) ; J4.2 107.51,47.43 v1(107.57,47.37) ; v1(84.66,51.28) 84.88,51.28 85.16,51 U1.34 ; U1.32 87.51,48.49 87.63,48.61 v1(87.63,49.02) ; R3.2 87.6,31.75 87.33,32.03 C27.1 v1(86.21,32.03) ; v1(81.28,43.81) U1.65 v1(82.55,43.81) ; J4.17 v1(107.52,39.92) ; U7.11 101.93,47.37 v1(103.12,47.37) ; U1.17 88.47,40.7 88.77,40.39 v1(88.77,40.13) ; J4.11 v1(107.57,42.93) ; U7.2 v1(103.09,42.84) ; U7.8 v1(103.11,45.83)
  TOP w0.305: U1.48 78.16,48.2 v1(78.74,47.62) ; U4.24 v1(18.97,40.97) ; U1.56 78.35,44.7 v1(78.74,45.09) ; U4.4 v1(21.8,50.97) ; U4.52 26.75,50.47 v1(26.16,51.05) ; U4.8 v1(21.79,48.97) ; U4.44 v1(26.43,46.47) ; U4.36 v1(26.47,42.47) ; U4.28 v1(18.94,38.97) ; U4.22 v1(18.98,41.97) ; v1(21.78,42.55) 21.59,42.55 21.52,42.47 U4.21 ; U1.26 85.64,45.2 85.52,45.09 v1(85.09,45.09) ; v1(21.97,45.85) 21.52,45.85 21.4,45.97 U4.14
  TOP w0.508: R8.1 v1(77.39,16.94) ; U8.3 34.84,58.8 v1(33.66,58.8) ; R26.1 v1(13.77,52.25) ; U5.3 v1(58.93,29.21) ; D1.2 57.53,65.94 v1(57.53,64.9) 57.84,64.59 C5.2 ; R21.1 v1(70.87,27.94) ; U8.2 v1(33.66,59.69) ; R20.1 v1(57.14,29.2) ; U6.1 v1(44.58,59.69) ; C1.2 v1(40.26,65.41)
  LYR_2 w0.66: 2.91,56.89 J3.2 ; J3.2 2.91,58.68 ; J3.2 4.71,58.68 ; J3.2 4.71,56.89 ; 89.91,13.07 S1.12 ; S1.12 89.91,14.87 ; S1.12 91.7,13.07 ; S1.12 91.7,14.87 ; 5.45,54.35 J3.3 ; J3.3 7.25,56.14 ; J3.3 5.45,56.14 ; J3.3 7.25,54.35 ; J3.6 4.71,53.6 ; J3.6 2.91,51.81 ; J3.6 2.91,53.6 ; J3.6 4.71,51.81 ; J3.10 4.71,46.73 ; J3.10 2.91,48.52 ; J3.10 4.71,48.52 ; J3.10 2.91,46.73 ; J5.1 66.17,70.86 ; J5.1 66.17,72.65 ; J5.1 64.38,72.65 ; J5.1 64.38,70.86 ; 84.83,14.87 S1.16 ; S1.16 86.62,13.07 ; S1.16 86.62,14.87 ; S1.16 84.83,13.07 ; 94.99,13.07 S1.8 ; S1.8 96.78,13.07 ; S1.8 96.78,14.87 ; S1.8 94.99,14.87 ; 79.75,13.07 S1.20 ; S1.20 81.54,14.87 ; S1.20 81.54,13.07 ; S1.20 79.75,14.87 ; J3.11 7.25,44.19 ; J3.11 5.45,45.98 ; J3.11 5.45,44.19 ; J3.11 7.25,45.98 ; J1.3 34.55,72.65 ; J1.3 32.76,70.86 ; J1.3 32.76,72.65 ; J1.3 34.55,70.86 ; JP6.1 16.9,22.99 ; JP6.1 15.11,21.2 ; JP6.1 16.9,21.2 ; JP6.1 15.11,22.99 ; 97.53,14.87 S1.6 ; S1.6 99.32,13.07 ; S1.6 99.32,14.87 ; S1.6 97.53,13.07 ; 30.22,70.86 J1.4 ; J1.4 32.01,72.65 ; J1.4 32.01,70.86 ; J1.4 30.22,72.65 ; J6.3 16.71,70.11 ; J6.3 16.71,65.43 ; J6.3 14.53,70.11 ; J6.3 14.53,65.43 ; J3.15 7.25,40.9 ; J3.15 7.25,39.11 ; J3.15 5.45,40.9 ; J3.15 5.45,39.11 ; 73.4,61.22 U3.4 ; U3.4 73.4,59.43 ; U3.4 75.19,59.43 ; U3.4 75.19,61.22 ; 17.98,69.68 J6.2 ; J6.2 22.66,69.68 ; J6.2 22.66,71.86 ; J6.2 17.98,71.86 ; 61.84,72.65 J5.2 ; J5.2 63.63,70.86 ; J5.2 61.84,70.86 ; J5.2 63.63,72.65 ; 88,70.86 J7.4 ; J7.4 89.8,72.65 ; J7.4 88,72.65 ; J7.4 89.8,70.86 ; 2.91,41.65 J3.14 ; J3.14 4.71,41.65 ; J3.14 4.71,43.44 ; J3.14 2.91,43.44 ; S1.10 94.24,13.07 ; S1.10 94.24,14.87 ; S1.10 92.45,14.87 ; S1.10 92.45,13.07 ; S1.14 89.16,14.87 ; S1.14 87.37,13.07 ; S1.14 87.37,14.87 ; S1.14 89.16,13.07 ; 14.98,28.95 JP2.3 ; JP2.3 14.98,30.74 ; JP2.3 16.77,28.95 ; JP2.3 16.77,30.74 ; J3.18 4.71,36.57 ; J3.18 4.71,38.36 ; J3.18 2.91,38.36 ; J3.18 2.91,36.57 ; 102.61,14.87 S1.2 ; S1.2 104.4,13.07 ; S1.2 102.61,13.07 ; S1.2 104.4,14.87 ; S1.4 101.86,14.87 ; S1.4 100.07,13.07 ; S1.4 101.86,13.07 ; S1.4 100.07,14.87 ; 82.29,14.87 S1.18 ; S1.18 84.08,13.07 ; S1.18 84.08,14.87 ; S1.18 82.29,13.07 ; 5.45,35.82 J3.19 ; J3.19 5.45,34.03 ; J3.19 7.25,34.03 ; J3.19 7.25,35.82 ; 5.45,49.27 J3.7 ; J3.7 5.45,51.06 ; J3.7 7.25,51.06 ; J3.7 7.25,49.27
  BOTTOM w0.254: C7.1 84.73,50.5 84.66,50.57 v1(84.66,51.28) ; v1(88.77,40.13) 87.78,40.13 C8.1 ; C9.1 v1(87.63,49.02) ; v1(103.12,47.37) 102.74,46.99 C13.1 ; v1(103.09,42.84) 102.74,43.18 C14.1
  BOTTOM w0.305: v1(18.97,40.97) 20.9,40.97 C21.1 ; v1(21.97,45.85) 21.82,46 C20.1 ; C10.2 v1(93.56,37.47)
  BOTTOM w0.381: C19.1 27.3,42.1 26.94,42.47 v1(26.47,42.47) ; C25.2 23.37,43.79 21.97,45.19 v1(21.97,45.85) ; v1(25.4,41.53) 25.4,40.41 C26.2 ; v1(98.65,36.95) 98.96,37.26 C11.1
  BOTTOM w0.508: C4.1 v1(59.25,57.47) ; C22.1 33.9,59.04 v1(33.66,58.8) ; C23.2 v1(35.13,55.3) ; C16.2 C15.2 v1(66.04,27.05) ; C17.2 v1(58.93,29.21) ; C3.2 v1(44.78,55.3) ; C24.2 v1(21.44,37.31) ; C2.2 v1(49.35,55.3)
  BOTTOM w0.635: C12.2 v1(92.23,54.33) ; C6.2 v1(83.03,54.25)
  vias: v1(75.56,35.56) v1(76.83,35.56) v1(78.74,46.35) v1(78.74,43.81) v1(78.74,42.55) v1(80.01,47.62) v1(80.01,46.35) v1(80.01,45.09) v1(80.01,43.81) v1(80.01,42.55) v1(80.01,41.27) v1(81.28,47.62) v1(81.28,46.35) v1(81.28,45.09) v1(81.28,42.55) v1(81.28,41.27) v1(82.55,47.62) v1(82.55,46.35) v1(82.55,45.09) v1(82.55,42.55) v1(82.55,41.27) v1(83.82,47.62) v1(83.82,46.35) v1(83.82,45.09) v1(83.82,43.81) v1(83.82,42.55) v1(83.82,41.27) v1(85.09,47.62) v1(85.09,46.35) v1(85.09,43.81)
0+: length 19.2
  TOP w0.127: U1.25 88.37,44.7 88.49,44.58 90.04,44.58 90.17,44.45 91.62,44.45 91.85,44.68 R39.1 92.3,44.68 92.53,44.45 100.71,44.45 101.1,44.84 U7.6 103.5,44.84 103.76,44.58 104.65,44.58 105,44.93 J4.7
0-: length 19.3
  TOP w0.127: J4.9 105.04,43.93 104.65,44.32 103.76,44.32 103.76,44.32 103.31,43.87 103.3,43.87 103.27,43.84 U7.4 101.07,43.84 100.71,44.2 92.53,44.2 92.3,43.97 R39.2 91.85,43.97 91.62,44.2 90.06,44.2 89.94,44.32 88.49,44.32 88.37,44.2 U1.24
1+: length 19.4
  TOP w0.127: J4.4 104.98,46.43 104.54,46 103.76,46 103.42,46.33 U7.9 101.07,46.33 100.71,45.97 98.91,45.97 98.66,46.23 92.61,46.23 92.38,46.46 R38.1 91.85,46.46 91.62,46.23 90.06,46.23 89.91,46.08 88.49,46.08 88.37,46.2 U1.28
1-: length 19.4
  TOP w0.127: J4.6 104.94,45.43 104.63,45.74 103.76,45.74 103.35,45.33 U7.7 101.1,45.33 100.71,45.72 98.81,45.72 98.55,45.97 92.58,45.97 92.35,45.75 R38.2 91.85,45.75 91.62,45.97 90.17,45.97 90.02,45.82 88.49,45.82 88.37,45.7 U1.27
2+: length 19.7
  TOP w0.127: U1.31 88.37,47.7 88.49,47.58 89.38,47.58 89.81,48.01 91.44,48.01 91.67,48.23 R37.1 92.35,48.23 92.58,48.01 98.91,48.01 99.55,47.37 100.71,47.37 101.17,47.83 U7.12 102.92,47.83 102.93,47.84 103.32,47.84 103.33,47.83 103.42,47.83 103.76,47.5 104.6,47.5 105.03,47.93 J4.1
2-: length 19.6
  TOP w0.127: J4.3 104.96,46.93 104.65,47.24 103.76,47.24 103.35,46.83 U7.10 100.99,46.83 100.71,47.12 99.44,47.12 98.81,47.75 92.71,47.75 92.48,47.52 R37.2 91.67,47.52 91.44,47.75 89.92,47.75 89.49,47.32 88.49,47.32 88.37,47.2 U1.30
//G0: length 38
  TOP w0.178: RN6.8 38.64,45.87 v1(35.81,43.05) ; U4.41 30.47,44.97 v1(30.73,44.7)
  BOTTOM w0.178: v1(30.73,44.7) 34.16,44.7 v1(35.81,43.05)
//G1: length 37.6
  TOP w0.178: RN6.7 38.12,46.38 v1(35.81,44.07) ; U4.42 29.09,45.47 29.1,45.47 v1(29.46,45.47)
  BOTTOM w0.178: v1(29.46,45.47) 29.83,45.47 29.84,45.47 31.1,45.47 31.51,45.06 34.82,45.06 v1(35.81,44.07)
//R0: length 44.8
  TOP w0.178: RN5.8 35.33,50.32 v1(34.67,49.66) ; v1(26.16,50.04) 25.15,49.02 23.4,49.02 22.96,49.47 U4.7
  BOTTOM w0.178: v1(26.16,50.04) 26.42,49.78 28.82,49.78 29.08,50.04 29.97,50.04 30.22,49.79 34.17,49.79 34.3,49.66 v1(34.67,49.66)
B0: length 13.5
  TOP w0.178: RN7.9 66.05,40.79 66.08,40.77 67.44,40.77 v1(67.94,41.27) 71.12,41.27 71.19,41.2 U1.63
  BOTTOM w0.178: v1(67.94,41.27) 67.46,40.79 RN7.9
B1: length 12
  TOP w0.178: U1.62 68.22,41.7 68.15,41.77 67.74,41.77 67.26,41.3 v1(66.65,41.3) RN7.10
  BOTTOM w0.178: v1(66.65,41.3) RN7.10
B2: length 13.5
  TOP w0.178: RN7.11 66.65,41.79 66.66,41.8 67.27,41.8 67.59,42.13 67.78,42.13 v1(67.94,42.29) 71.12,42.29 71.21,42.2 U1.61
  BOTTOM w0.178: RN7.11 67.45,41.79 v1(67.94,42.29)
B3: length 12
  TOP w0.178: U1.60 68.24,42.7 68.15,42.79 67.74,42.79 67.25,42.3 v1(66.67,42.3) RN7.12
  BOTTOM w0.178: v1(66.67,42.3) RN7.12
B4: length 13.5
  TOP w0.178: U1.59 71.23,43.2 71.12,43.31 v1(67.94,43.31) 67.58,43.31 67.33,43.06 67.12,43.06 66.87,42.8 66.67,42.8 66.67,42.79 RN7.13
  BOTTOM w0.178: v1(67.94,43.31) 67.43,42.79 RN7.13
B5: length 12
  TOP w0.178: RN7.14 v1(66.66,43.3) 66.67,43.3 66.78,43.41 67.15,43.41 67.54,43.8 68.15,43.8 68.25,43.7 U1.58
  BOTTOM w0.178: v1(66.66,43.3) RN7.14
B6: length 13.8
  TOP w0.178: RN7.15 66.66,43.79 66.66,43.8 66.85,43.8 67.38,44.32 v1(67.94,44.32) 68.82,45.2 U1.55
  BOTTOM w0.178: RN7.15 66.44,43.79 66.44,43.8 67.42,43.8 v1(67.94,44.32)
B7: length 12.3
  TOP w0.178: RN7.16 v1(66.65,44.3) 68.05,45.7 U1.54
  BOTTOM w0.178: RN7.16 v1(66.65,44.3)
BSEL/SCL: length 65.7
  TOP w0.152: U1.15 v1(85.16,37.59) 85.16,31.42 85.47,31.11 87,31.11 87.15,30.96 87.27,30.96 88.35,29.88 88.35,27.73 87,26.37 87,20.83 88.07,19.75 94.05,19.75 S1.7 R16.1
  BOTTOM w0.152: JP3.2 91.57,62.36 91.57,54.61 90.81,53.85 90.81,51.69 91.88,50.61 91.88,40.45 91.31,39.88 89.55,39.88 89.27,39.6 88.24,39.6 86.23,37.59 v1(85.16,37.59)
C+: length 19.5
  TOP w0.127: U1.22 88.37,43.2 88.49,43.08 89.49,43.08 89.89,42.67 91.85,42.67 R40.1 92.3,42.67 99.21,42.67 99.46,42.93 100.71,42.93 101.12,43.34 U7.3 103.48,43.34 103.76,43.05 104.52,43.05 104.89,43.43 J4.10
C-: length 19.5
  TOP w0.127: U1.21 88.37,42.7 88.49,42.82 89.38,42.82 89.79,42.42 91.85,42.42 R40.2 92.3,42.42 99.31,42.42 99.57,42.67 100.71,42.67 101.05,42.34 U7.1 103.3,42.34 103.76,42.8 104.52,42.8 104.89,42.43 J4.12
CEC: length 12.1
  TOP w0.152: TP2.1 97.49,38.1 97.99,38.6 U2.1 99.02,38.8 99.06,38.85 99.06,39.24 99.47,39.65 100.99,39.65 103.27,41.93 J4.13
CTL1: length 21
  TOP w0.152: U1.8 81.67,36.25 81.56,36.14 81.56,35.74 81.67,35.64 81.67,33.27 JP1.3 83.9,27.38 83.9,25.2 84.98,24.12 R12.1 S1.15
CTL2: length 20
  TOP w0.152: U1.7 81.16,31.23 JP1.2 81.36,27.38 81.36,25.2 82.44,24.12 R11.1 S1.17
CTL3: length 19.2
  TOP w0.152: U1.6 80.67,30.07 80.64,30.05 JP1.1 78.82,27.38 78.82,25.2 79.9,24.12 R10.1 S1.19
D_PCLK: length 17.2
  TOP w0.152: R33.1 R34.1 68.57,34.09 68.58,34.1 v1(68.58,35.18) ; U1.57 v1(73.66,44.2)
  BOTTOM w0.152: v1(68.58,35.18) 73.66,40.26 v1(73.66,44.2)
DDC_C: length 51.9
  TOP w0.152: v1(102.36,38.99) 102.36,40.13 103.15,40.92 J4.15 ; v1(98.42,38.1) U2.2
  BOTTOM w0.152: JP3.3 93.98,62.23 93.98,57.53 97.03,54.48 99.44,54.48 105.41,48.51 105.41,42.29 104.01,40.89 99.19,40.89 98.42,40.13 v1(98.42,38.1) 97.92,37.59 97.92,36.58 98.23,36.26 101.28,36.26 101.98,36.96 101.98,38.61 v1(102.36,38.99)
DDC_D: length 35.8
  TOP w0.152: U2.5 101.22,38.1 101.6,38.48 102.9,38.48 103.02,38.61 v1(103.38,38.61) 103.38,39.75 104.05,40.42 J4.16
  BOTTOM w0.152: JP4.3 99.95,59.05 105.28,53.72 105.28,49.11 105.74,48.65 105.74,42.15 105.28,41.7 105.28,41.27 103.38,39.37 v1(103.38,38.61)
DE: length 22.5
  TOP w0.178: v1(72.26,40.01) 78.42,40.01 78.67,39.76 U1.2 ; RN8.6 59.95,37.85 59.96,37.85 v1(60.33,37.85)
  BOTTOM w0.178: v1(72.26,40.01) 64.14,40.01 61.98,37.85 60.7,37.85 60.69,37.85 v1(60.33,37.85) 59.96,37.85 59.95,37.85 RN8.6
DKEN: length 47.2
  TOP w0.152: v1(93.22,50.04) 87.88,50.04 86.66,48.82 84.84,48.82 84.67,48.99 U1.35 ; S1.5 R17.1 99.3,24.12 99.95,24.77 99.95,26.29 101.22,27.56 101.22,33.4 100.2,34.42 95,34.42 v1(94.49,34.92)
  BOTTOM w0.152: v1(94.49,34.92) 94.49,35.94 94.04,36.39 94.04,39.05 92.58,40.51 92.58,49.4 v1(93.22,50.04)
DSEL/SDA: length 52.8
  TOP w0.152: U1.14 84.67,37.95 84.58,37.87 v1(84.58,36.96) ; S1.9 R15.1 93.78,24.12 93.79,24.13 94.23,24.13 94.61,24.51 94.61,26.29 93.73,27.18 v1(93.73,28.19)
  BOTTOM w0.152: v1(93.73,28.19) 93.22,28.7 93.22,30.35 91.44,32.13 89.41,32.13 v1(84.58,36.96) 86.49,36.96 88.8,39.27 89.41,39.27 89.64,39.5 91.82,39.5 92.21,39.89 92.21,50.3 93.79,51.88 93.79,54.55 92.71,55.63 JP4.2
EDGE/HTPLG: length 29.3
  TOP w0.152: U1.9 82.16,36.33 82.19,36.3 v1(82.19,35.94) ; S1.13 R13.1 88.89,24.12 89.66,24.89 89.66,28.07 TP1.1 R6.1 93.97,29.64 93.73,29.88 Q1.2
  BOTTOM w0.152: v1(82.19,35.94) 84.03,35.94 84.38,35.59 84.43,35.59 TP1.1
FBIN: length 1.9
  TOP w0.152: R23.1 60.95,33.22 60.9,33.18 U5.1
G0: length 13.5
  TOP w0.178: U1.53 69.24,46.2 69.09,46.35 v1(67.94,46.35) 67.46,45.87 RN6.9
  BOTTOM w0.178: v1(67.94,46.35) 67.46,45.87 RN6.9
G1: length 12
  TOP w0.178: U1.52 75.4,46.7 75.39,46.71 69.24,46.71 69.1,46.85 67.67,46.85 67.19,46.38 v1(66.65,46.38) RN6.10
  BOTTOM w0.178: RN6.10 v1(66.65,46.38)
G2: length 13.5
  TOP w0.178: U1.51 69.26,47.2 69.09,47.37 v1(67.94,47.37) 67.78,47.21 67.52,47.21 67.33,47.02 67.01,47.02 66.88,46.88 66.66,46.88 66.65,46.87 RN6.11
  BOTTOM w0.178: RN6.11 67.45,46.87 v1(67.94,47.37)
G3: length 12
  TOP w0.178: RN6.12 v1(66.67,47.38) 66.67,47.37 67.18,47.37 67.68,47.87 69.23,47.87 69.39,47.7 U1.50
  BOTTOM w0.178: RN6.12 v1(66.67,47.38)
G4: length 18.5
  TOP w0.178: RN6.13 67.06,47.87 67.58,48.39 v1(67.94,48.39) 68.83,48.39 72.14,51.69 78.23,51.69 78.67,51.26 U1.47
  BOTTOM w0.178: v1(67.94,48.39) 67.43,47.87 RN6.13
G5: length 17.6
  TOP w0.178: RN6.14 v1(66.66,48.38) 67.02,48.38 67.54,48.9 68.84,48.9 71.99,52.04 78.38,52.04 79.16,51.26 U1.46
  BOTTOM w0.178: RN6.14 v1(66.66,48.38)
G6: length 19.7
  TOP w0.178: U1.45 79.67,51.26 78.53,52.4 71.84,52.4 68.84,49.4 v1(67.94,49.4) 67.44,49.4 66.91,48.88 66.7,48.88 66.7,48.87 RN6.15
  BOTTOM w0.178: v1(67.94,49.4) 67.42,48.87 RN6.15
G7: length 18.8
  TOP w0.178: RN6.16 v1(66.65,49.38) 67.18,49.91 68.85,49.91 71.69,52.76 78.67,52.76 80.16,51.27 U1.44
  BOTTOM w0.178: RN6.16 v1(66.65,49.38)
HOT_PLUG: length 25.3
  TOP w0.152: J4.19 106.05,37.72 104.9,36.58 102.34,36.58 102.03,36.88 R35.2 100.84,37.47 100.7,37.6 U2.4 100.37,36.49 99.82,35.94 89.15,35.94 88.27,35.05 88.27,33.46 88.25,33.45 R4.2 87.55,33.02 87.27,32.74 C27.2
HS: length 24.5
  TOP w0.178: v1(74.55,38.73) 72.01,38.73 71.88,38.86 v1(60.33,38.86) 59.96,38.86 59.94,38.85 RN8.8 ; v1(79.5,36.7) 79.67,36.87 U1.4
  BOTTOM w0.178: RN8.8 59.94,38.85 59.96,38.86 v1(60.33,38.86) ; v1(74.55,38.73) 75.56,37.72 76.58,37.72 77.6,36.7 v1(79.5,36.7)
ISEL/RST: length 23.3
  TOP w0.152: S1.11 R14.1 91.24,24.12 91.25,24.13 91.69,24.13 91.95,24.38 91.95,26.29 92.71,27.05 v1(92.71,28.32) ; v1(84.58,36.07) 84.1,36.55 84.1,37.16 84.16,37.22 U1.13
  BOTTOM w0.152: v1(84.58,36.07) 84.96,36.07 89.53,31.5 91.19,31.5 92.71,29.97 v1(92.71,28.32)
LVDSVCC: length 6.5
  TOP w0.305: U4.13 21.54,46.47 v1(21.93,46.86)
  BOTTOM w0.305: v1(21.93,46.86) 21.46,46.86 21.31,46.71 C20.2
  BOTTOM w0.381: v1(21.93,46.86) 22.29,46.51 C25.1 22.72,47.16 FB5.2
MSEN/PO1: length 16.5
  TOP w0.152: v1(83.19,35.31) 83.19,35.66 83.16,35.68 U1.11 ; TP4.1 76.83,27.61 76.2,26.97 R9.1
  BOTTOM w0.152: TP4.1 82.68,35.05 82.93,35.05 v1(83.19,35.31)
PCLK: length 7.2
  TOP w0.178: R24.2 R32.2 57.14,34.1 57.15,34.11 57.15,34.54 v1(59.22,36.61) RN8.5
  BOTTOM w0.178: v1(59.22,36.61) RN8.5
PCLK_IN: length 3.5
  TOP w0.152: R24.1 58.43,31.32 58.42,31.31 58.42,30.99 58.93,30.48 U5.2
PCLK_OUT: length 1.9
  TOP w0.152: R34.2 R22.1
PD: length 37.7
  TOP w0.152: C18.2 108.15,21.6 108.14,21.59 S1.1 R18.1 103.07,24.12 103.06,24.13 v1(102.49,24.13) ; v1(83.31,34.04) 82.67,34.68 82.67,35.73 82.68,35.74 82.68,36.14 82.67,36.15 U1.10
  BOTTOM w0.152: v1(102.49,24.13) 101.47,24.13 100.84,24.77 100.84,26.04 99.44,27.43 89.92,27.43 v1(83.31,34.04)
PDN: length 12.6
  TOP w0.152: JP2.2 14.22,34.04 14.22,36.45 18.26,40.49 19.12,40.49 19.14,40.47 U4.25
PLLVCC: length 5.3
  TOP w0.305: U4.23 v1(21.79,41.47)
  BOTTOM w0.305: v1(21.79,41.47) 22.86,40.4 C24.1 ; v1(21.79,41.47) 21.12,41.47 C21.2 ; v1(21.79,41.47) 22.23,41.91 FB6.2
R0: length 20.7
  TOP w0.178: RN5.9 66.27,50.32 66.29,50.29 67.44,50.29 v1(67.94,50.8) 69.24,50.8 71.55,53.11 78.82,53.11 80.67,51.27 U1.43
  BOTTOM w0.178: RN5.9 66.05,50.32 66.07,50.3 67.45,50.3 v1(67.94,50.8)
R1: length 19.9
  TOP w0.178: U1.42 81.16,51.27 78.97,53.47 71.4,53.47 69.24,51.31 67.54,51.31 67.03,50.8 v1(66.67,50.8) 65.64,50.8 RN5.10
  BOTTOM w0.178: RN5.10 65.64,50.8 v1(66.67,50.8)
R2: length 21.9
  TOP w0.178: RN5.11 66.88,51.32 67.38,51.82 v1(67.94,51.82) 69.25,51.82 71.25,53.82 79.12,53.82 81.67,51.27 U1.41
  BOTTOM w0.178: RN5.11 67.45,51.32 v1(67.94,51.82)
R3: length 21.1
  TOP w0.178: U1.40 82.16,51.28 79.26,54.18 71.11,54.18 69.12,52.2 68.26,52.2 68.15,52.31 67.36,52.31 67.03,51.98 66.84,51.98 v1(66.67,51.82) 65.62,51.82 RN5.12
  BOTTOM w0.178: v1(66.67,51.82) 65.62,51.82 RN5.12
R4: length 23.1
  TOP w0.178: U1.39 82.67,51.28 79.41,54.53 70.96,54.53 69.26,52.83 v1(67.94,52.83) 67.38,52.83 66.88,52.34 66.69,52.34 66.68,52.32 RN5.13
  BOTTOM w0.178: RN5.13 67.43,52.32 v1(67.94,52.83)
R5: length 22.2
  TOP w0.178: RN5.14 66.28,52.82 66.29,52.83 v1(66.67,52.83) 66.84,53 67.03,53 67.37,53.34 69.26,53.34 70.81,54.89 79.56,54.89 83.16,51.28 U1.38
  BOTTOM w0.178: RN5.14 66.29,52.82 66.31,52.83 v1(66.67,52.83)
R6: length 24.3
  TOP w0.178: U1.37 83.67,51.29 79.71,55.25 70.66,55.25 69.27,53.85 v1(67.94,53.85) 67.38,53.85 66.88,53.35 66.5,53.35 66.46,53.32 RN5.15
  BOTTOM w0.178: RN5.15 66.46,53.32 66.47,53.33 66.88,53.33 66.89,53.32 67.42,53.32 v1(67.94,53.85)
R7: length 23.4
  TOP w0.178: RN5.16 65.65,53.85 v1(66.67,53.85) 67.18,54.36 68.96,54.36 70.21,55.6 79.85,55.6 84.16,51.29 84.16,51.08 84.16,51.07 U1.36
  BOTTOM w0.178: RN5.16 65.65,53.85 v1(66.67,53.85)
RXCLKIN+: length 20.5
  TOP w0.127: J3.16 4.99,41.18 5.11,41.18 5.31,40.98 8.23,40.98 8.64,41.39 8.64,41.93 8.74,42.04 9.29,42.04 9.4,41.93 9.4,41.39 9.8,40.98 12.41,40.98 14.48,43.05 15.35,43.05 R27.2 15.88,42.62 16.31,43.05 17.12,43.05 18.16,44.09 19.31,44.09 19.44,43.97 U4.18
RXCLKIN-: length 20.3
  TOP w0.127: U4.17 19.44,44.47 19.31,44.35 18.06,44.35 17.02,43.31 16.31,43.31 15.88,43.74 R27.1 15.35,43.31 14.37,43.31 12.3,41.24 9.91,41.24 9.65,41.49 9.65,42.04 9.4,42.29 8.64,42.29 8.38,42.04 8.38,41.49 8.13,41.24 5.42,41.24 5.21,41.45 5.21,41.75 5.42,41.96 5.77,41.96 J3.13
RXIN0+: length 20.8
  TOP w0.127: 15.88,50.24 16.2,50.57 16.38,50.57 18.86,48.09 19.31,48.09 19.44,47.97 U4.10 ; 15.88,50.24 R31.2 ; 15.88,50.24 15.44,50.67 13.74,50.67 8.15,56.26 4.83,56.26 J3.4
RXIN0-: length 20.5
  TOP w0.127: J3.1 5.97,57.78 5.46,57.28 5.46,56.77 5.71,56.52 8.26,56.52 13.84,50.93 15.44,50.93 15.88,51.36 ; U4.9 19.44,48.47 19.31,48.35 18.96,48.35 16.49,50.82 16.41,50.82 15.88,51.36 ; 15.88,51.36 R31.1
RXIN1+: length 20.4
  TOP w0.127: U4.12 19.44,46.97 19.31,47.09 17.83,47.09 16.79,48.13 16.4,48.13 R30.2 15.88,47.7 15.44,48.13 14.5,48.13 11.32,51.31 9.88,51.31 9.78,51.2 9.78,50.82 9.38,50.42 8.53,50.42 8.13,50.82 8.13,51.05 7.87,51.31 4.95,51.31 J3.8
RXIN1-: length 20.5
  TOP w0.127: U4.11 19.44,47.47 19.31,47.35 17.93,47.35 16.89,48.39 16.4,48.39 R30.1 15.88,48.82 15.44,48.39 14.61,48.39 11.43,51.56 9.78,51.56 9.53,51.31 9.53,50.93 9.27,50.67 8.64,50.67 8.38,50.93 8.38,51.16 7.98,51.56 5.46,51.56 5.21,51.82 5.21,52.45 5.46,52.7 J3.5
RXIN2+: length 20.3
  TOP w0.127: J3.12 4.88,46.15 8.13,46.15 8.38,46.41 8.38,47.52 8.49,47.62 9.67,47.62 9.78,47.52 9.78,46.56 10.18,46.15 12.54,46.15 13.1,45.59 15.35,45.59 R29.2 16.4,45.59 17.42,45.59 17.92,45.09 19.31,45.09 19.44,44.97 U4.16
RXIN2-: length 20.6
  TOP w0.127: J3.9 5.46,47.62 5.21,47.37 5.21,46.66 5.46,46.41 8.02,46.41 8.13,46.51 8.13,47.62 8.38,47.88 9.78,47.88 10.03,47.62 10.03,46.66 10.29,46.41 12.65,46.41 13.21,45.85 15.35,45.85 R29.1 16.4,45.85 17.53,45.85 18.03,45.35 19.31,45.35 19.44,45.47 U4.15
RXIN3+: length 20.4
  TOP w0.127: J3.20 4.83,35.94 8.89,35.94 13.46,40.51 15.35,40.51 R28.2 16.48,40.6 16.6,40.6 19.09,43.09 19.31,43.09 19.44,42.97 U4.20
RXIN3-: length 20.6
  TOP w0.127: U4.19 19.44,43.47 19.31,43.35 18.98,43.35 16.49,40.85 16.31,40.85 R28.1 15.35,40.77 13.36,40.77 8.78,36.19 5.46,36.19 5.21,36.45 5.21,37.21 5.46,37.47 J3.17
SCL: length 24.2
  TOP w0.254: JP3.1 93.85,67.18 93.85,67.44 93.98,67.56 J7.2 ; JP3.1 88.14,61.47 83.31,61.47 U3.6 ; JP3.1 87.63,66.04 R19.2
SDA: length 35.1
  TOP w0.254: J7.3 89.79,73.41 87.63,73.41 86.56,72.34 86.56,70.48 ; JP4.1 83.19,59.05 U3.5 80.39,61.85 80.39,68.71 82.19,70.5 86.54,70.5 86.56,70.48 ; 86.56,70.48 R25.2
TVDD: length 15.9
  TOP w0.254: U1.23 v1(88.9,43.7)
  TOP w0.381: U1.29 v1(88.86,46.7)
  BOTTOM w0.381: v1(88.9,43.7) 88.9,46.26 88.86,46.29 v1(88.86,46.7) 88.86,47.08 ; v1(89.41,51.27) 88.86,50.73 88.86,47.08 ; 88.86,47.08 88.67,47.27 C9.2
  BOTTOM w0.635: FB3.2 89.52,54.06 89.38,53.92 C12.1 89.38,51.46 89.41,51.44 v1(89.41,51.27)
VREF: length 24.2
  TOP w0.152: v1(75.07,20.94) R7.1 R8.2 ; v1(78.99,35.18) 78.99,37.78 79.16,37.95 U1.3
  BOTTOM w0.152: v1(78.99,35.18) 77.98,35.18 74.42,31.62 74.42,21.59 v1(75.07,20.94)
VS: length 27.2
  TOP w0.178: v1(80.01,35.69) 80.01,36.06 80.16,36.21 U1.5 ; RN8.7 60.97,38.35 60.97,38.35 v1(61.34,38.35) 70.74,38.35 71.98,37.11 v1(74.7,37.11)
  BOTTOM w0.178: v1(61.34,38.35) 60.97,38.35 60.97,38.35 RN8.7 ; v1(80.01,35.69) 77.85,35.69 76.43,37.11 v1(74.7,37.11)
N14860968: length 86.9
  BOTTOM w0.508: JP6.2 14.61,19.56 13.59,18.54 13.59,10.16 16.13,7.62 J2.1 J2.3 J2.5 J2.7 J2.9 J2.11 J2.13 J2.15 J2.17 J2.19 J2.21 J2.23 J2.25 J2.27 J2.31 J2.33 J2.35 J2.37 J2.39 J2.41 J2.43 J2.45 J2.47 J2.49 J2.51 J2.55
N14861406: length 5
  TOP w0.152: R5.2 90.68,40.64 89.62,41.7 U1.19
N14862082: length 2.4
  BOTTOM w0.305: v1(64.01,30.99) 64.95,30.05 C15.1
  vias: v1(61.34,26.8) v1(62.23,26.8) v1(62.99,30.99) v1(65.02,24.51) v1(65.02,23.5) v1(65.02,22.61)
N15107145: length 3.2
  TOP w0.152: R2.2 JP2.1
N15438976: length 9.7
  TOP w1.016: J6.1 20.32,62.48 21.84,60.96 D4.1
N15439034: length 11
  TOP w0.762: 53.09,63.5 55.88,60.71 JP7.1 56.9,59.05 57.77,59.93 D3.1
  vias: v1(45.09,64.77) v1(46.35,64.77) v1(47.24,61.98) v1(47.24,58.42) v1(47.62,64.77) v1(48.13,57.53) v1(48.9,64.77) v1(49.15,58.42) v1(50.16,64.77) v1(51.44,64.77)
N15440280: length 5.1
  TOP w0.254: JP5.1 U3.1
N15440284: length 5.1
  TOP w0.254: U3.2 JP5.2
N15440292: length 5.1
  TOP w0.254: JP5.3 U3.3
N15476881: length 2.4
  TOP w0.305: D1.1 R1.1
N15551732: length 3.5
  TOP w0.152: R4.1 R3.1 90.96,31.75 91.11,31.9 Q1.1
N15559932: length 2.4
  TOP w0.152: R6.2 D2.1
N15593216: length 4.6
  TOP w0.254: U3.7 83.82,63.5 TP3.1
N15691374: length 69.4
  TOP w0.178: v1(37.49,26.06) 36.86,26.06 33.66,22.86 33.66,6.35 J2.14
  BOTTOM w0.178: RN1.15 50.78,53.32 37.49,40.03 v1(37.49,26.06)
N15691376: length 69.9
  TOP w0.178: v1(38.13,27.33) 37.37,27.33 31.11,21.08 31.11,6.35 J2.12
  BOTTOM w0.178: RN1.14 50.92,52.82 38.13,40.03 v1(38.13,27.33)
N15691378: length 70.6
  TOP w0.178: J2.10 28.57,6.35 28.57,19.56 37.62,28.6 v1(38.76,28.6)
  BOTTOM w0.178: v1(38.76,28.6) 38.76,40.03 51.05,52.32 RN1.13
N15691380: length 72.2
  TOP w0.178: J2.4 21.08,6.22 21.08,14.35 39.15,32.41 v1(40.67,32.41)
  BOTTOM w0.178: RN1.10 51.46,50.82 40.67,40.03 v1(40.67,32.41)
N15691382: length 71.2
  TOP w0.178: J2.8 26.04,6.35 26.04,17.78 38.13,29.87 v1(39.4,29.87)
  BOTTOM w0.178: v1(39.4,29.87) 39.4,40.03 51.19,51.82 RN1.12
N15691384: length 72.8
  TOP w0.178: J2.2 18.29,6.48 18.29,12.32 39.65,33.68 v1(41.3,33.68)
  BOTTOM w0.178: RN1.9 51.72,50.32 41.3,39.91 v1(41.3,33.68)
N15691386: length 71.7
  TOP w0.178: v1(40.03,31.14) 38.64,31.14 23.5,16 23.5,6.35 J2.6
  BOTTOM w0.178: v1(40.03,31.14) 40.03,40.03 51.32,51.32 RN1.11
N15693021: length 68.6
  TOP w0.178: v1(36.86,24.79) 36.2,24.13 36.2,6.35 J2.16
  BOTTOM w0.178: v1(36.86,24.79) 36.86,40.14 50.54,53.82 RN1.16
N15693494: length 61.5
  TOP w0.178: v1(40.64,28.57) 40.64,20.57 46.48,14.73 46.48,6.22 J2.24
  BOTTOM w0.178: v1(40.64,28.57) 41.78,28.57 45.72,32.51 45.72,39.5 53.6,47.38 RN2.12
N15693496: length 60.5
  TOP w0.178: J2.22 43.69,6.48 43.69,16.51 40.01,20.19 v1(40.01,27.3)
  BOTTOM w0.178: RN2.11 53.73,46.87 46.35,39.5 46.35,32.38 41.27,27.3 v1(40.01,27.3)
N15693498: length 59.6
  TOP w0.178: J2.20 41.4,6.22 41.4,17.78 39.37,19.81 v1(39.37,26.04)
  BOTTOM w0.178: RN2.10 53.87,46.38 46.99,39.5 46.99,32.13 40.89,26.04 v1(39.37,26.04)
N15693502: length 58.5
  TOP w0.178: J2.18 38.73,6.35 v1(38.73,24.77)
  BOTTOM w0.178: v1(38.73,24.77) 40.51,24.77 47.62,31.88 47.62,39.37 54.13,45.87 RN2.9
N15693504: length 64.5
  TOP w0.178: 55.24,5.08 53.98,6.35 53.98,10.54 42.55,21.97 v1(42.55,32.38)
  BOTTOM w0.178: v1(42.55,32.38) 43.05,32.38 43.81,33.15 43.81,39.5 53.19,48.87 RN2.15
N15693506: length 63.6
  TOP w0.178: v1(41.91,31.11) 41.91,21.46 51.44,11.94 51.44,6.35 J2.28
  BOTTOM w0.178: v1(41.91,31.11) 42.8,31.11 44.45,32.77 44.45,39.5 53.33,48.38 RN2.14
N15693508: length 62.5
  TOP w0.178: v1(41.27,29.84) 41.27,20.95 49.02,13.21 49.02,6.22 J2.26
  BOTTOM w0.178: v1(41.27,29.84) 42.16,29.84 45.09,32.77 45.09,39.5 53.46,47.87 RN2.13
N15694906: length 54.5
  TOP w0.178: J2.50 79.25,6.48 79.25,8.64 73.91,13.97 62.23,13.97 v1(56.52,19.68)
  BOTTOM w0.178: RN4.8 55.36,38.85 54.61,38.1 54.61,21.59 v1(56.52,19.68)
N15694908: length 54.6
  TOP w0.178: v1(56.52,20.95) 62.87,14.61 74.8,14.61 80.52,8.89 81.15,8.89 81.92,8.13 81.92,6.35 J2.52
  BOTTOM w0.178: v1(56.52,20.95) 55.24,22.23 55.24,37.47 56.13,38.35 RN4.7
N15694910: length 55.3
  TOP w0.178: 85.72,5.08 84.45,6.35 84.45,8.64 83.44,9.65 81.28,9.65 75.69,15.24 63.5,15.24 v1(56.52,22.23)
  BOTTOM w0.178: RN4.6 56.77,37.85 55.88,36.96 55.88,22.86 v1(56.52,22.23)
N15694912: length 55.9
  TOP w0.178: v1(56.52,23.5) 64.14,15.88 76.58,15.88 82.3,10.16 85.6,10.16 87,8.76 87,6.35 J2.56
  BOTTOM w0.178: RN4.5 57.16,37.35 56.52,36.7 v1(56.52,23.5)
N15695898: length 64.1
  TOP w0.178: J2.42 69.09,6.48 69.09,10.16 67.82,11.43 59.94,11.43 47.62,23.75 v1(47.62,29.97)
  BOTTOM w0.178: RN3.13 55.37,42.79 51.44,38.86 51.44,32.89 48.51,29.97 v1(47.62,29.97)
N15695900: length 66.2
  TOP w0.178: v1(48.26,31.24) 48.26,24.26 60.45,12.06 70.1,12.06 71.88,10.29 71.88,6.22 J2.44
  BOTTOM w0.178: RN3.14 55.23,43.3 50.8,38.86 50.8,32.89 49.15,31.24 v1(48.26,31.24)
N15695902: length 61.7
  TOP w0.178: J2.40 66.67,6.35 66.67,9.02 64.9,10.79 59.44,10.79 46.99,23.24 v1(46.99,28.7)
  BOTTOM w0.178: v1(46.99,28.7) 48.13,28.7 52.07,32.64 52.07,38.86 55.5,42.3 RN3.12
N15695904: length 67.6
  TOP w0.178: v1(48.9,32.51) 48.9,24.89 61.09,12.7 71.63,12.7 74.17,10.16 74.17,6.48 J2.46
  BOTTOM w0.178: v1(48.9,32.51) 49.4,32.51 50.16,33.27 50.16,38.86 55.1,43.79 RN3.15
N15695906: length 68.8
  TOP w0.178: v1(49.53,33.78) 49.53,25.4 61.59,13.34 72.64,13.34 76.71,9.27 76.71,6.48 J2.48
  BOTTOM w0.178: v1(49.53,33.78) 49.53,38.96 54.86,44.3 RN3.16
N15695908: length 59.5
  TOP w0.178: J2.38 64.26,6.22 64.26,8.26 62.36,10.16 58.93,10.16 46.35,22.73 v1(46.35,27.43)
  BOTTOM w0.178: RN3.11 55.64,41.79 52.7,38.86 52.7,32.51 47.62,27.43 v1(46.35,27.43)
N15695910: length 57.6
  TOP w0.178: J2.36 61.59,6.35 61.59,8.26 60.33,9.53 58.42,9.53 45.72,22.23 v1(45.72,26.04)
  BOTTOM w0.178: v1(45.72,26.04) 47.12,26.04 53.34,32.26 53.34,38.86 55.77,41.3 RN3.10
N15695912: length 55.5
  TOP w0.178: J2.34 59.05,6.35 59.05,7.75 58.79,8.01 58.79,8.04 58.2,8.62 58.18,8.62 45.09,21.72 v1(45.09,24.89)
  BOTTOM w0.178: v1(45.09,24.89) 46.86,24.89 53.98,32 53.98,38.73 56.03,40.79 RN3.9
